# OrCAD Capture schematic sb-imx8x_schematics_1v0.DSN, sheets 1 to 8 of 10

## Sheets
1 09. LVDS LCD: size A3; title: 9. LVDS LCD; rev: 1.0; note: 8010055003
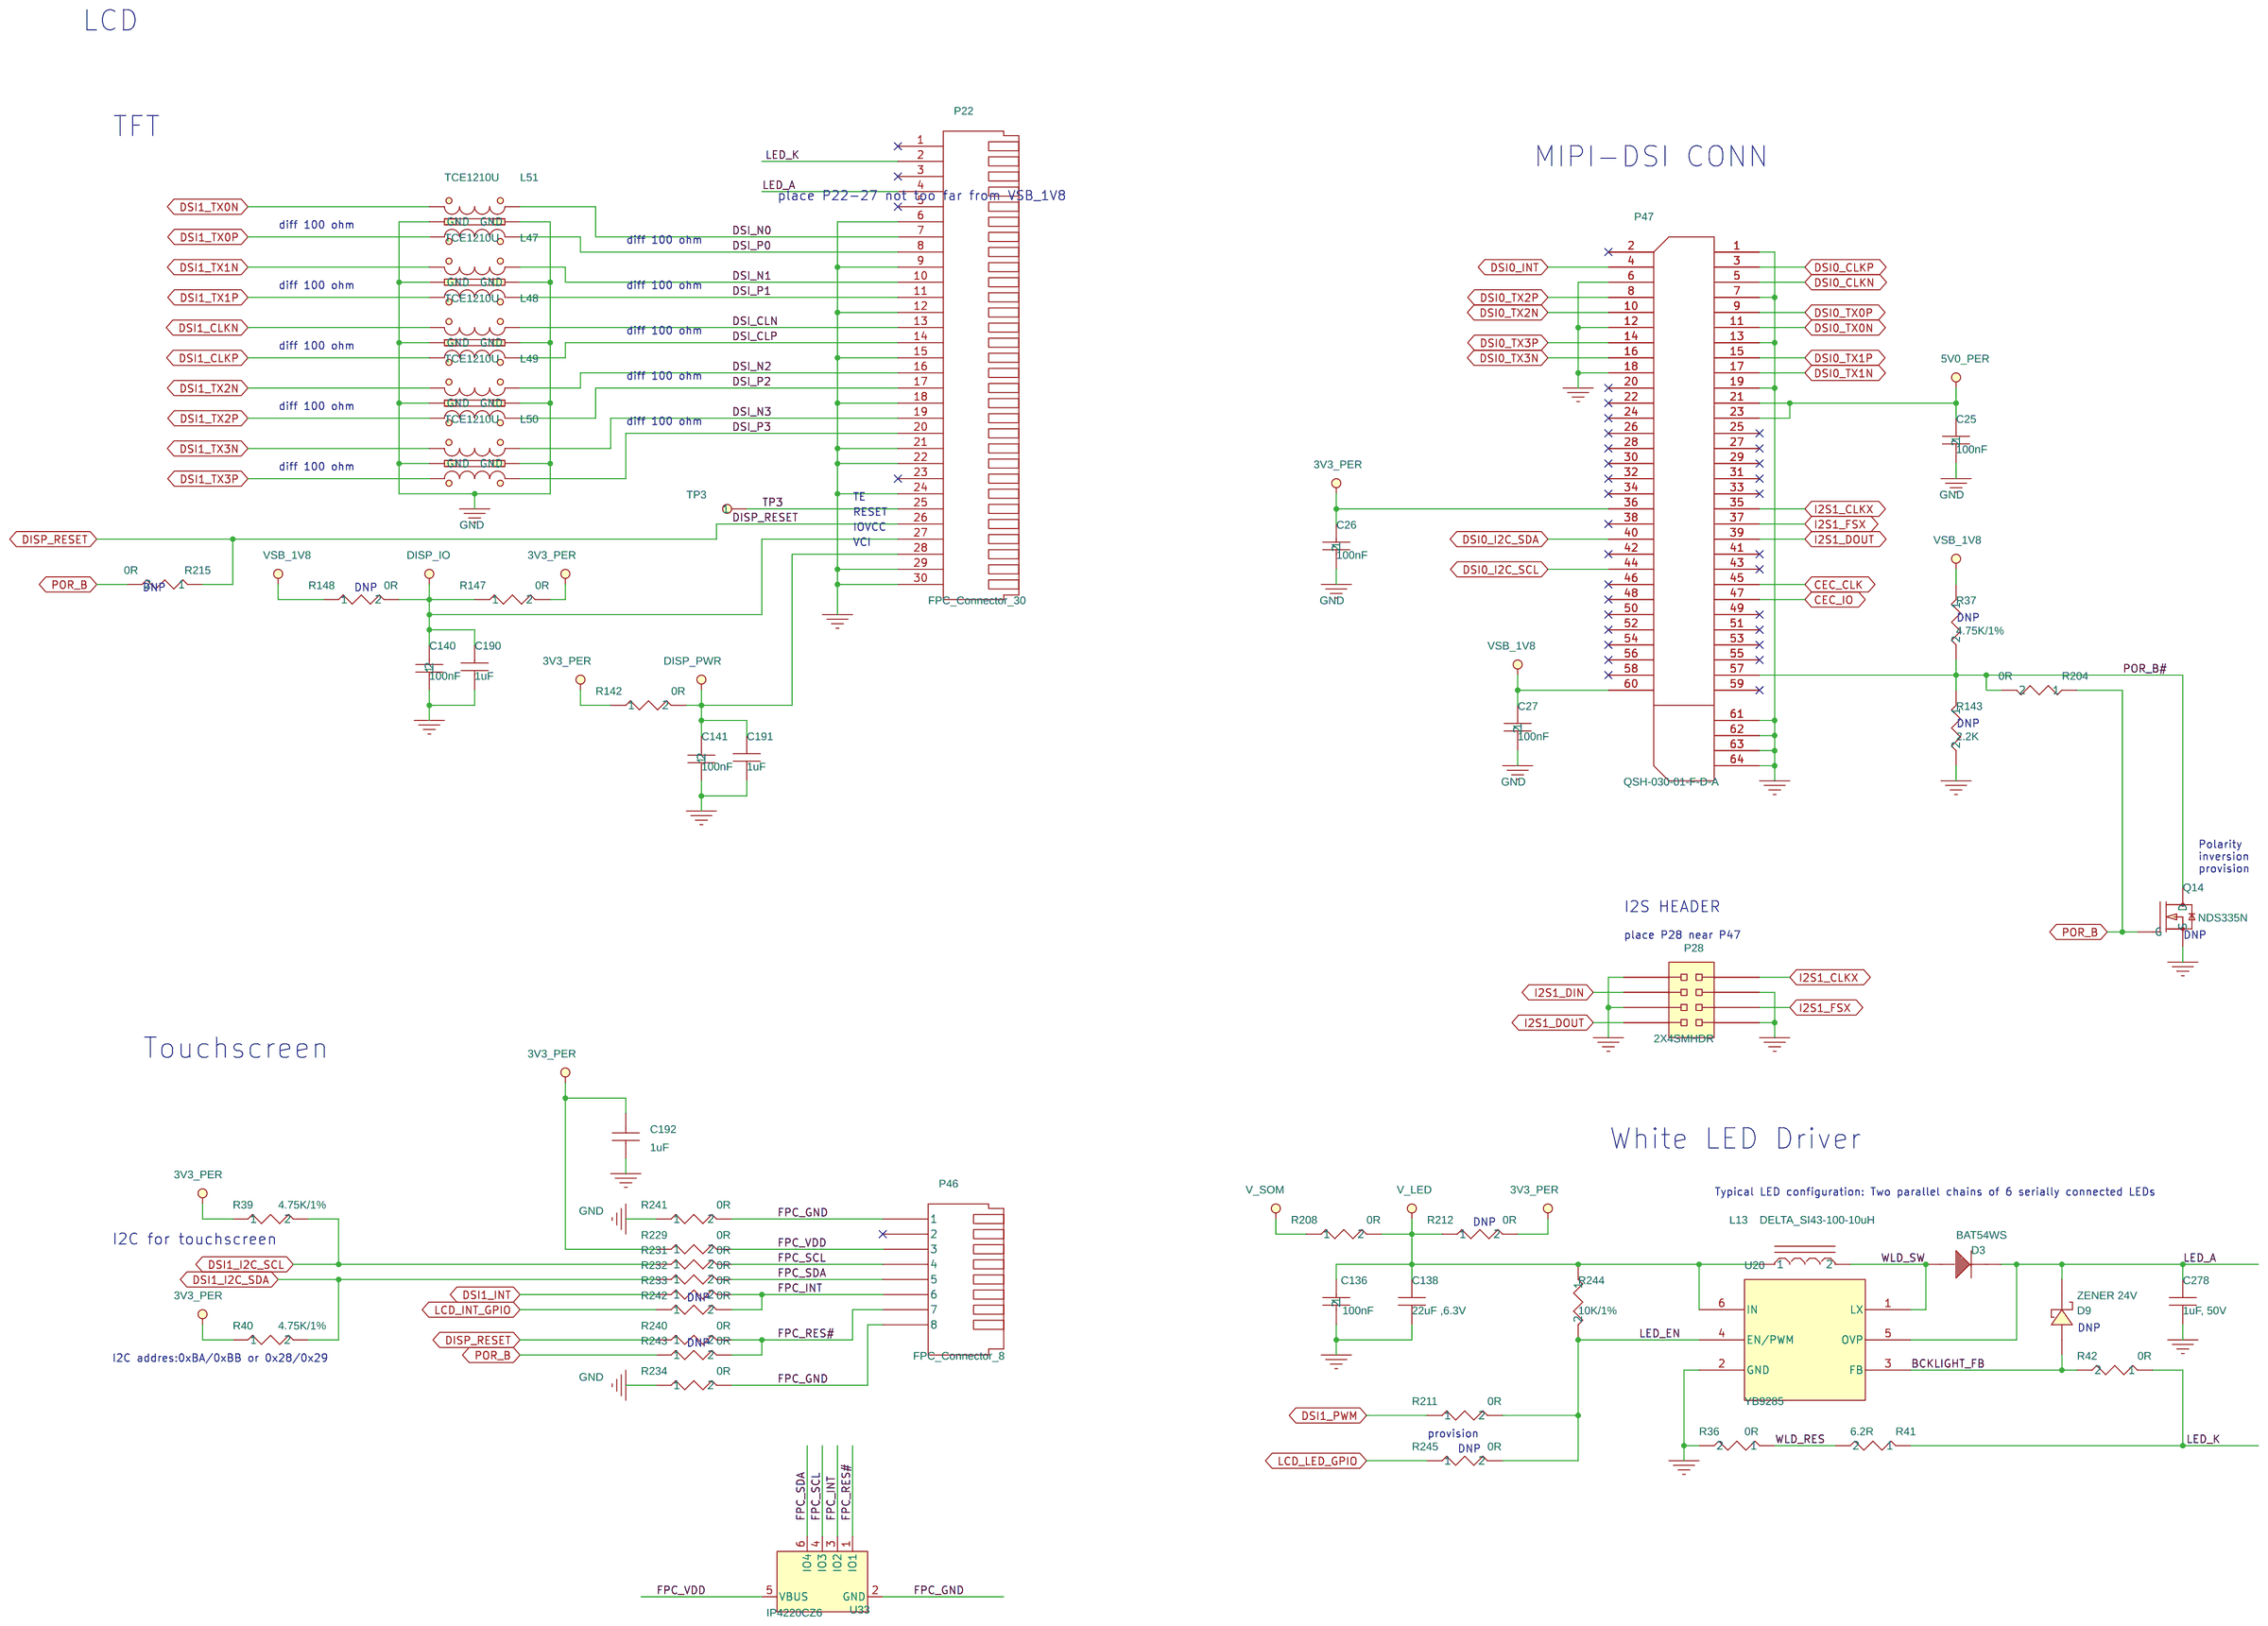
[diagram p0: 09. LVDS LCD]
2 10. MECHANICS: size B; title: 10. MECHANICS; note: 8000064001
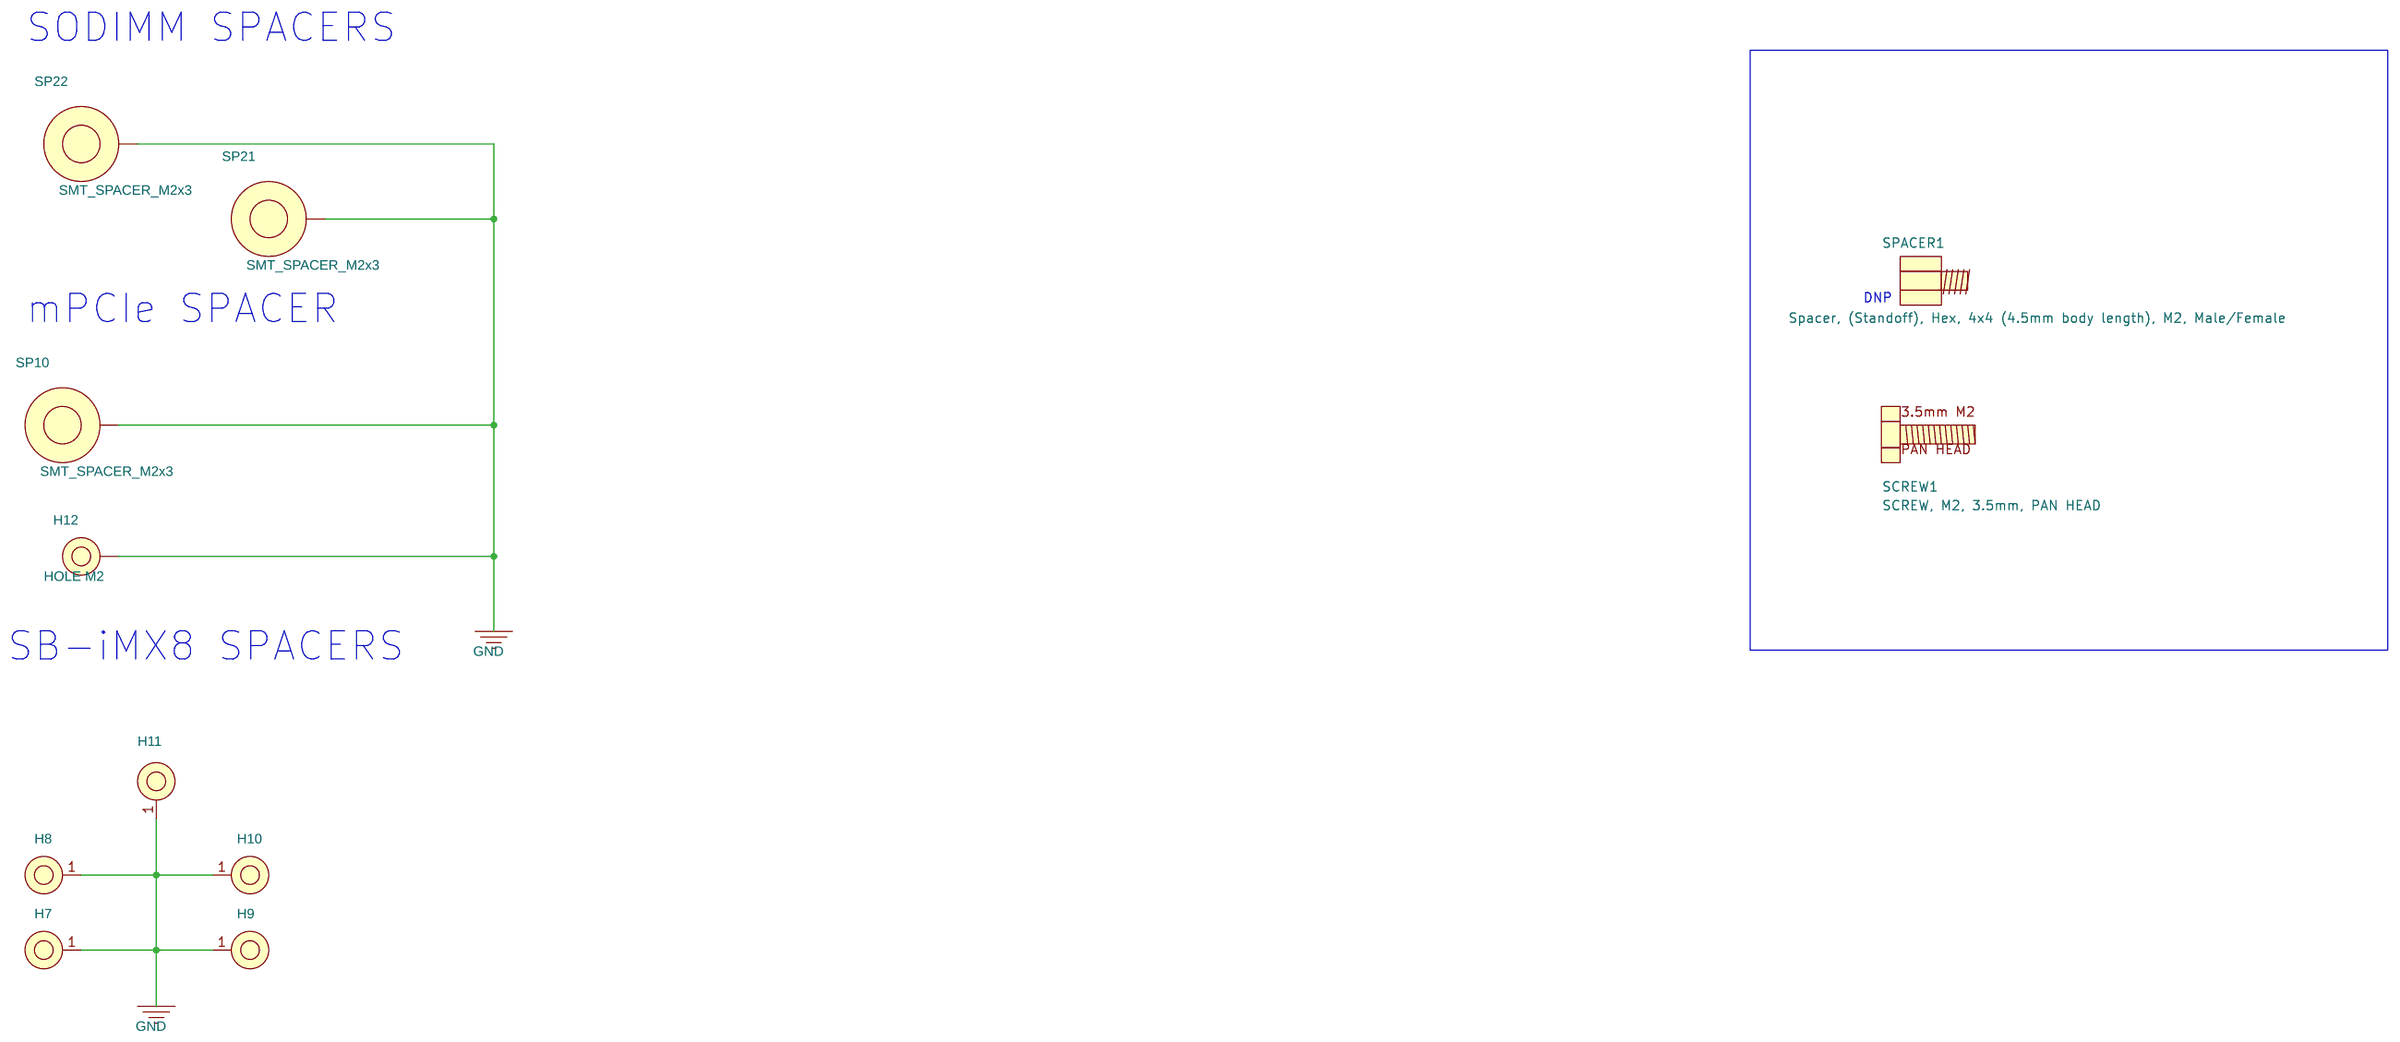
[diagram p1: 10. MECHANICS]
3 01. BLOCK & POWER DIAGRAM: size C; title: 01. BLOCK DIAGRAM
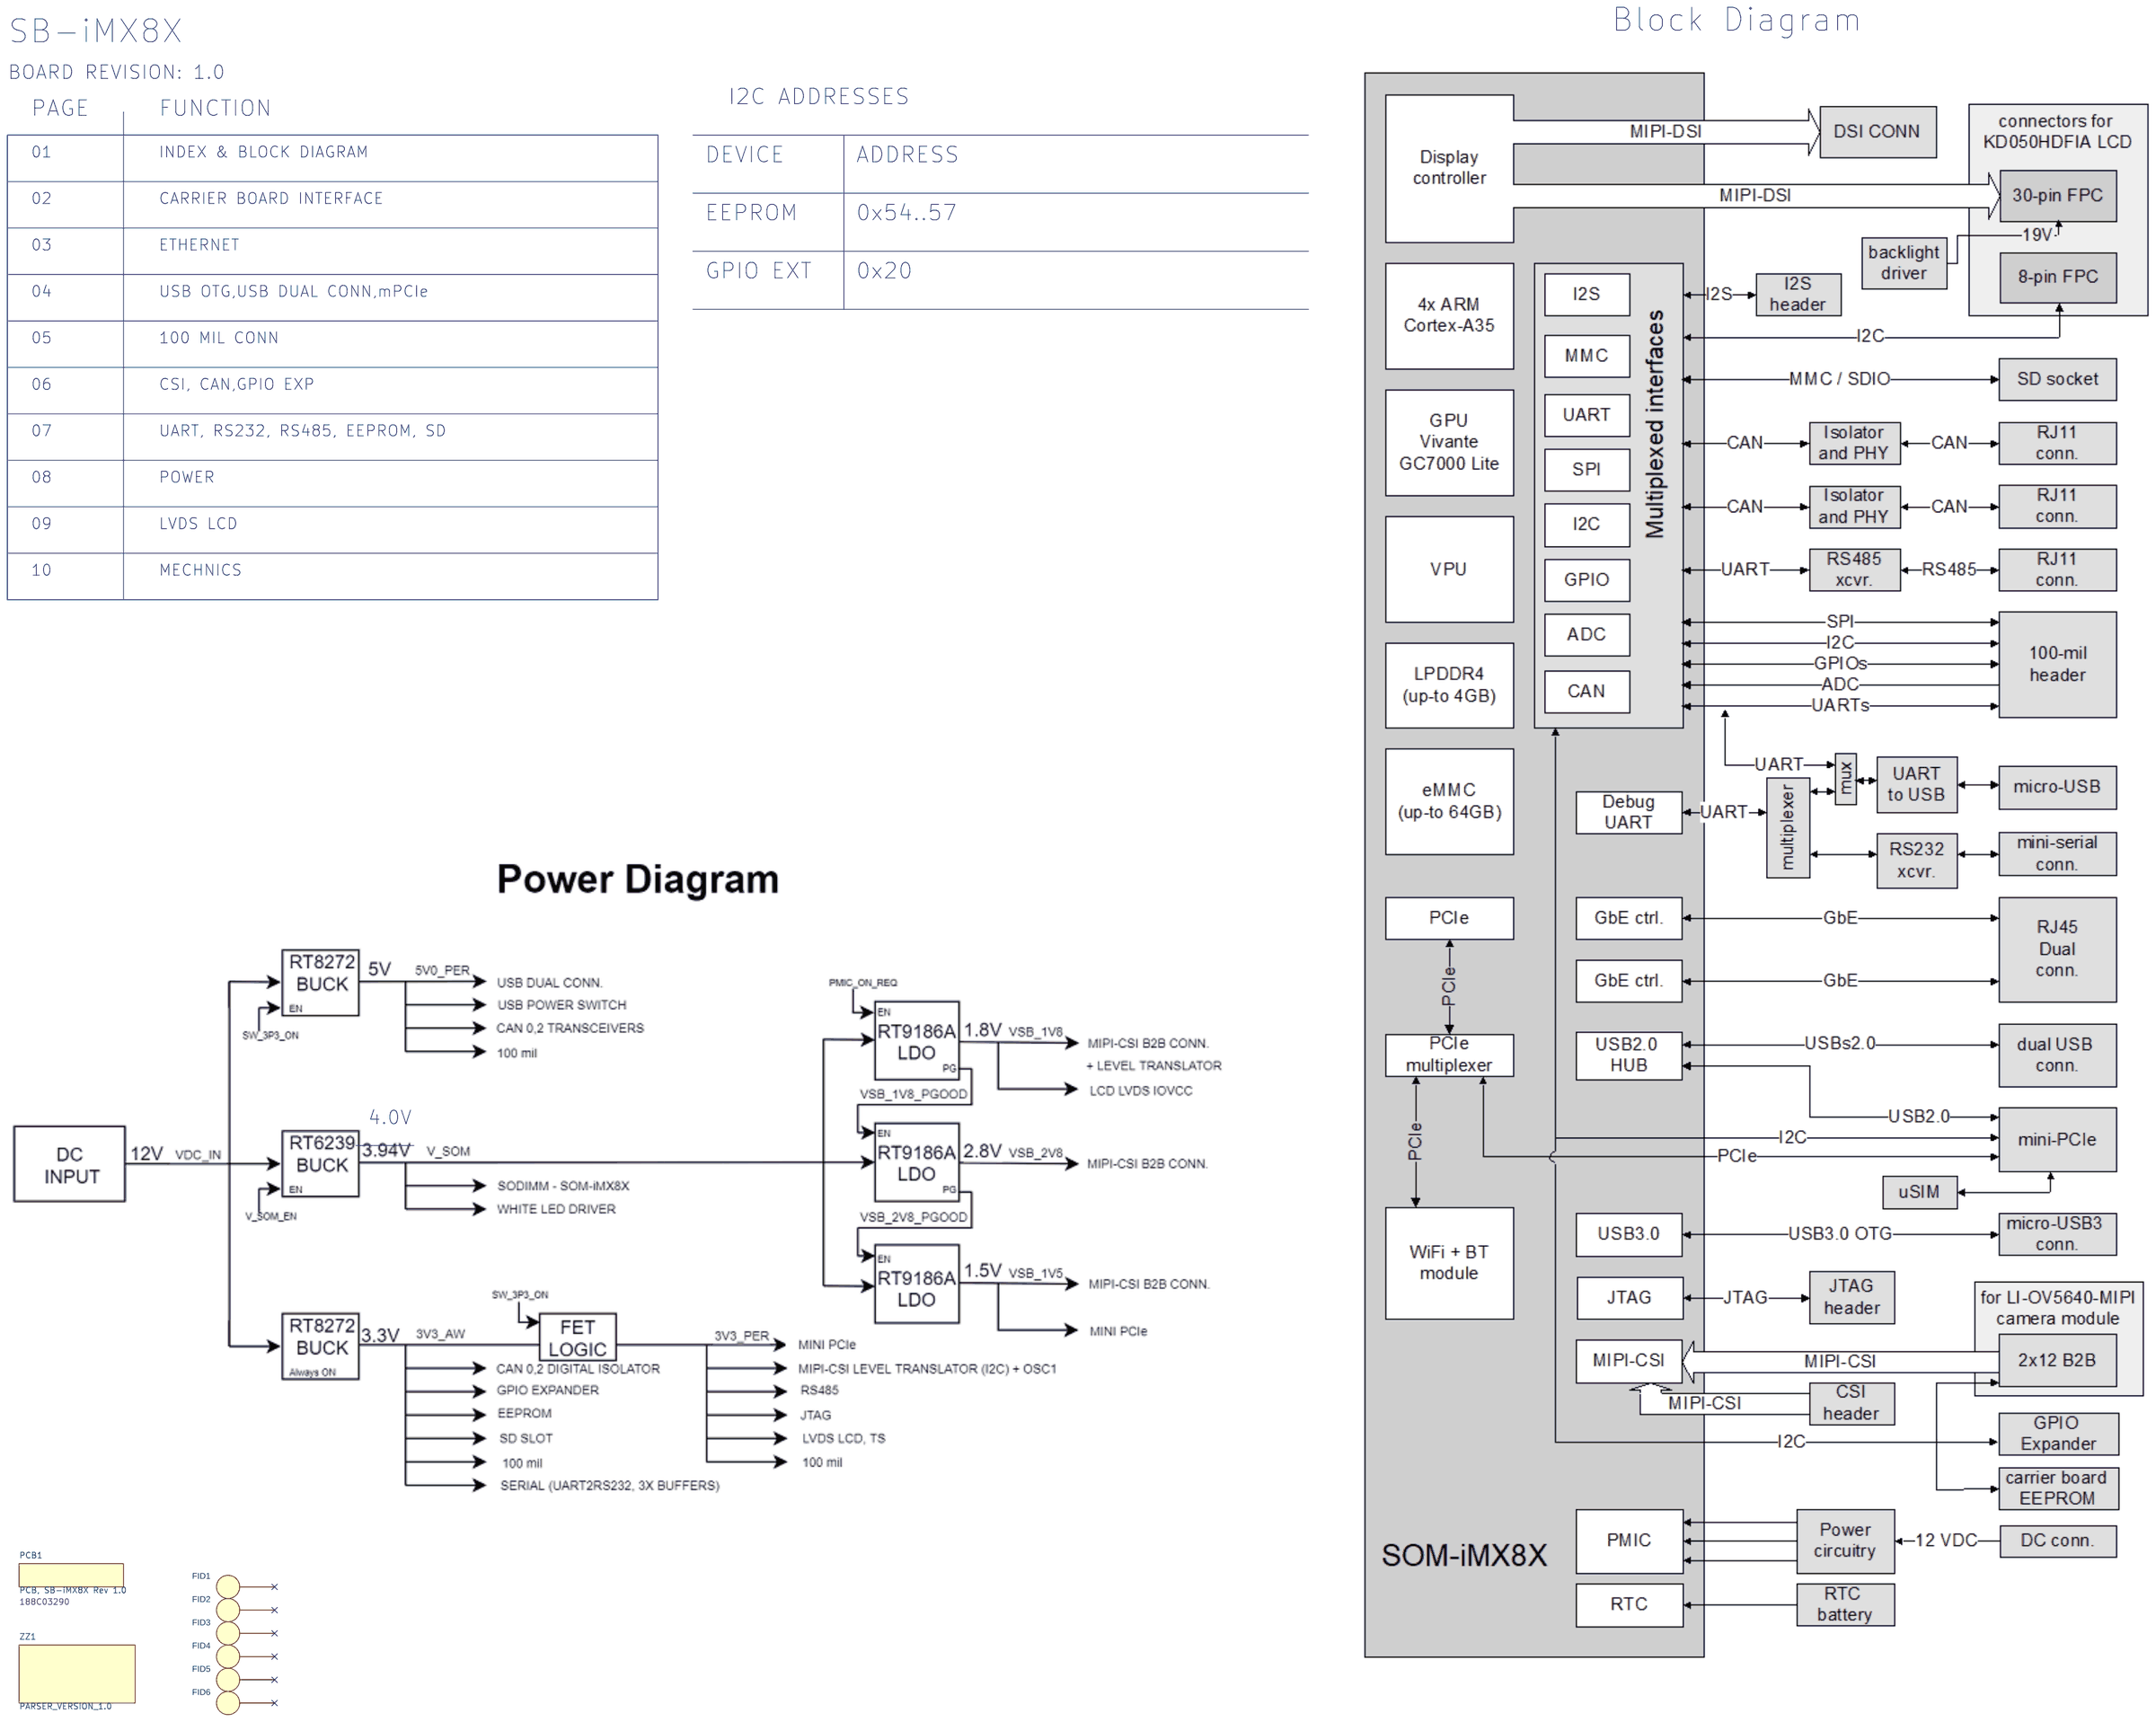
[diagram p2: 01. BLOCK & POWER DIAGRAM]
4 02. SODIMM: size C; title: 02. SODIMM; note: 8000064001
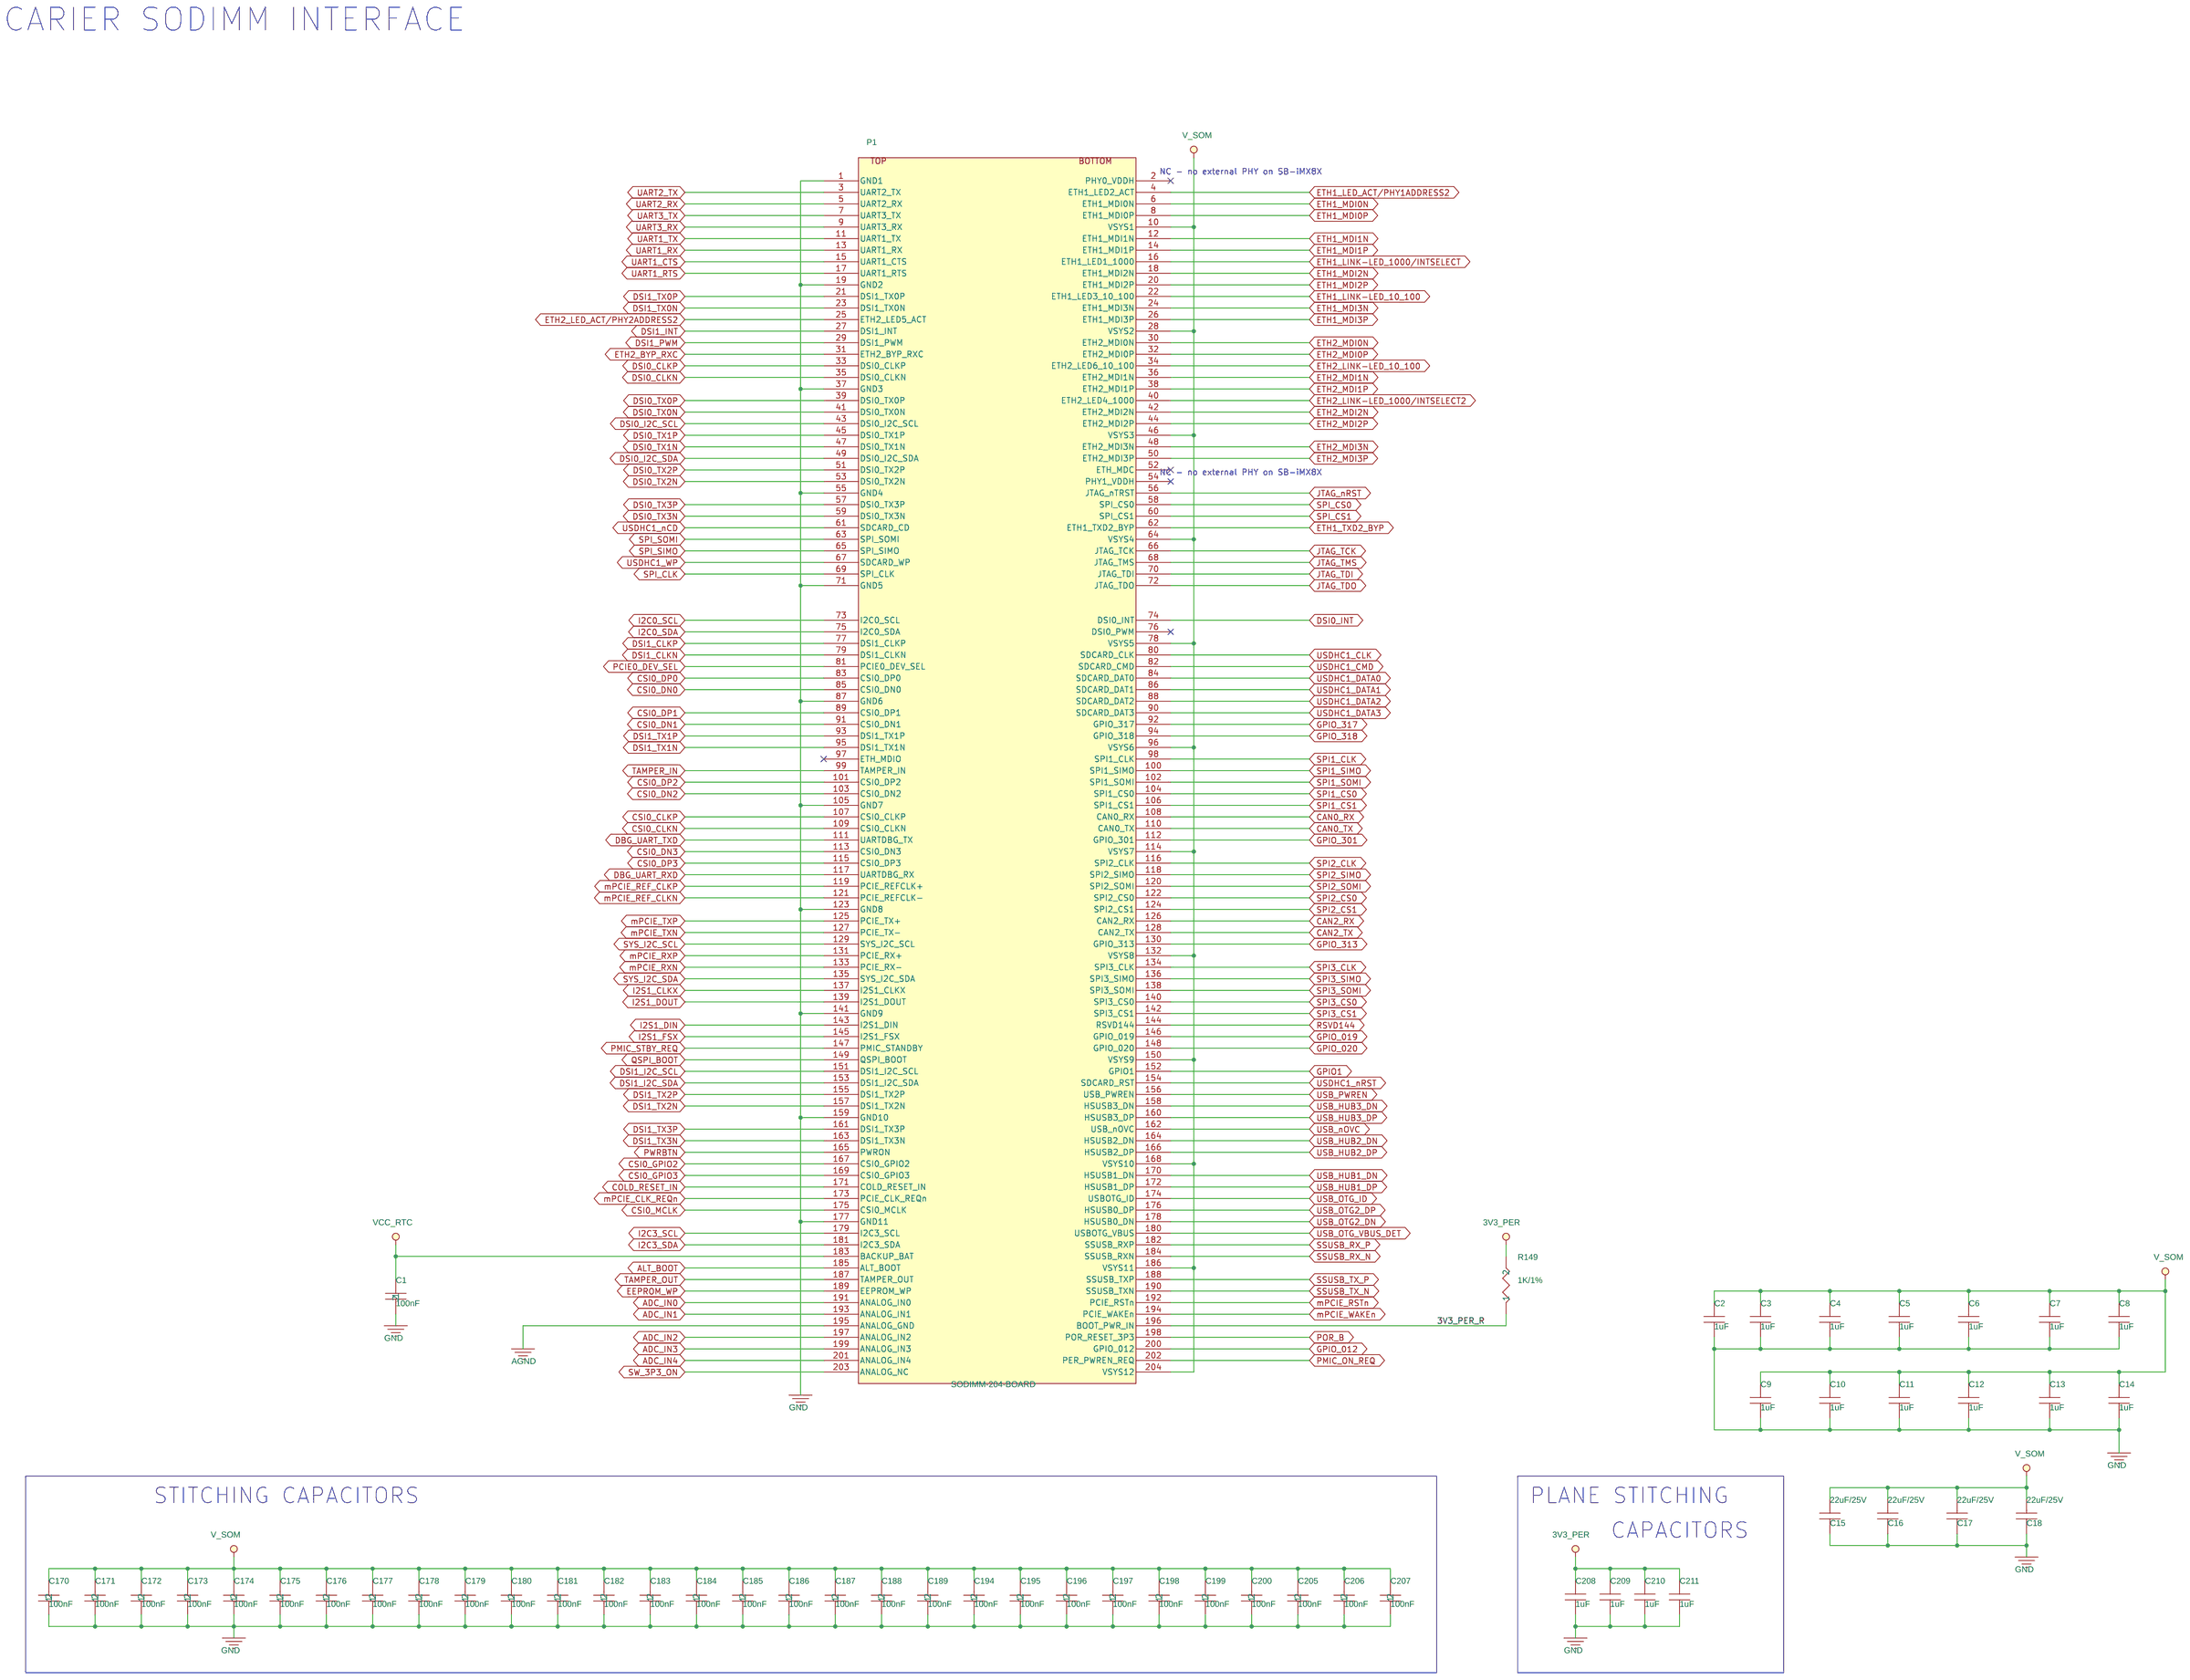
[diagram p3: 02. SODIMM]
5 03. ETHERNET 1 , 2: size B; title: 03. ETHERNET 1 , 2; note: 8000064001
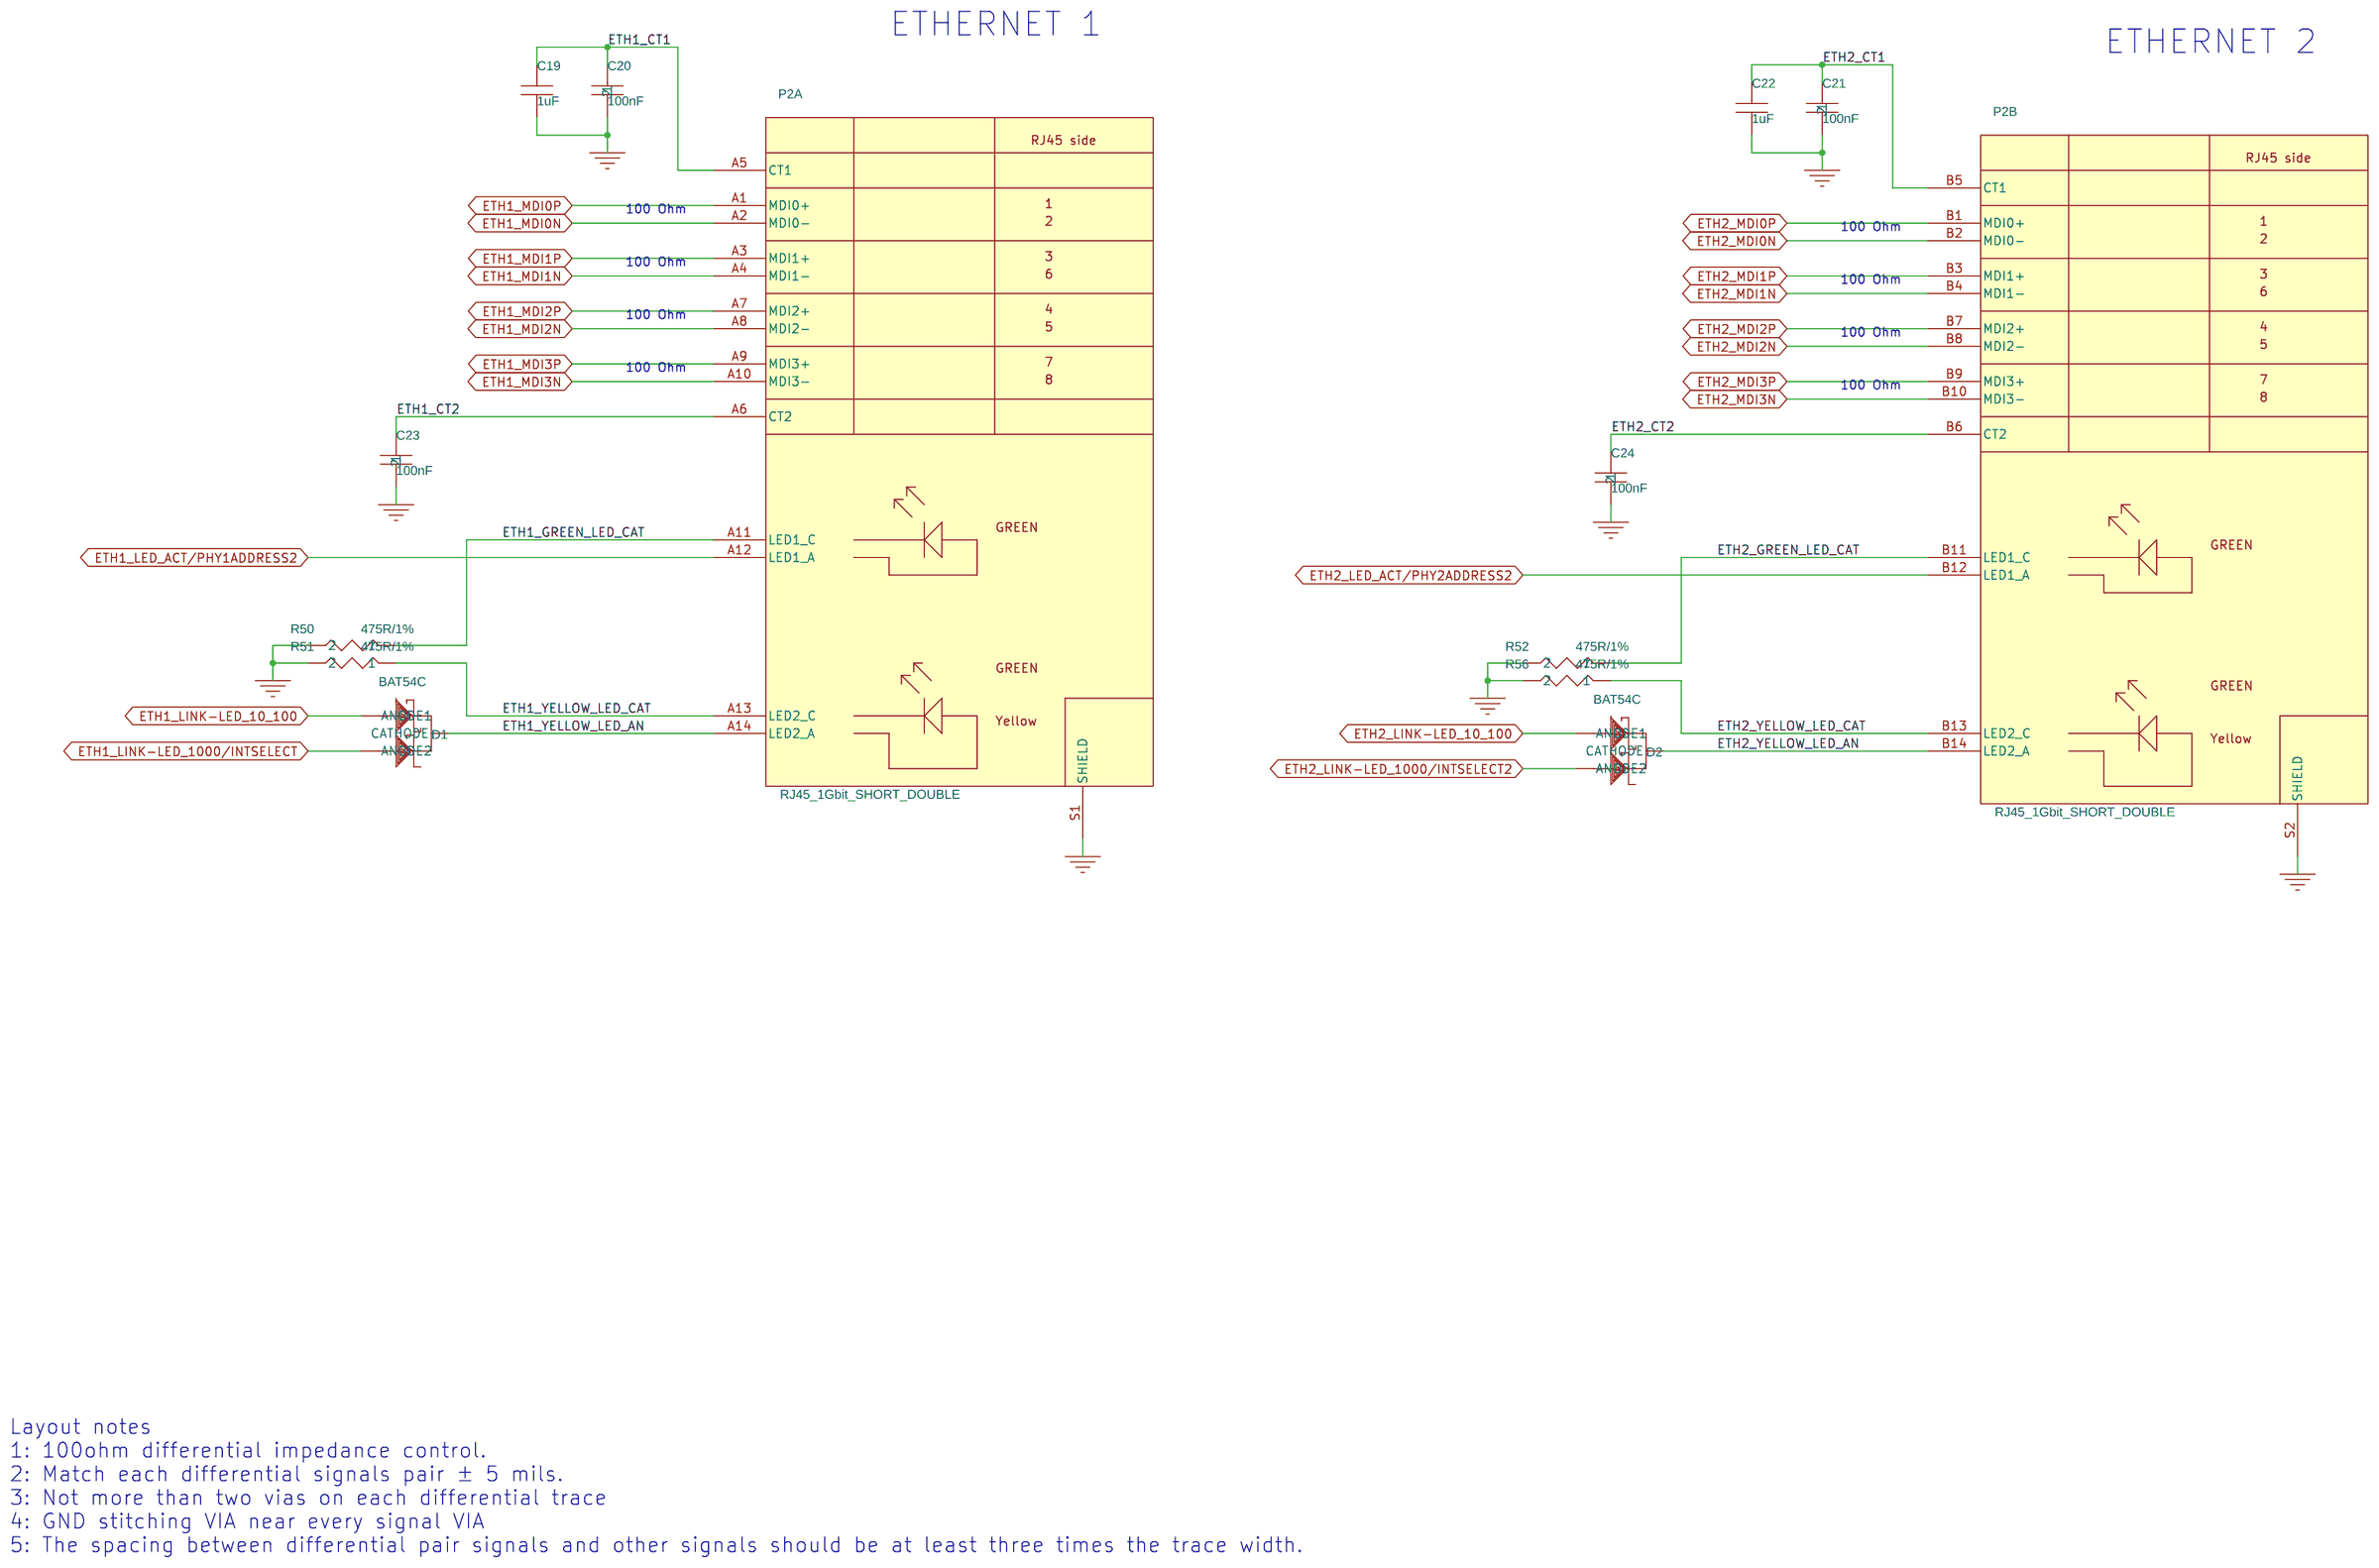
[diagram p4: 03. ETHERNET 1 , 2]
6 04. USB OTG,USB DUAL CONN,mPCIe: size C; title: 04. USB OTG,USB DUAL CONN,mPCIe
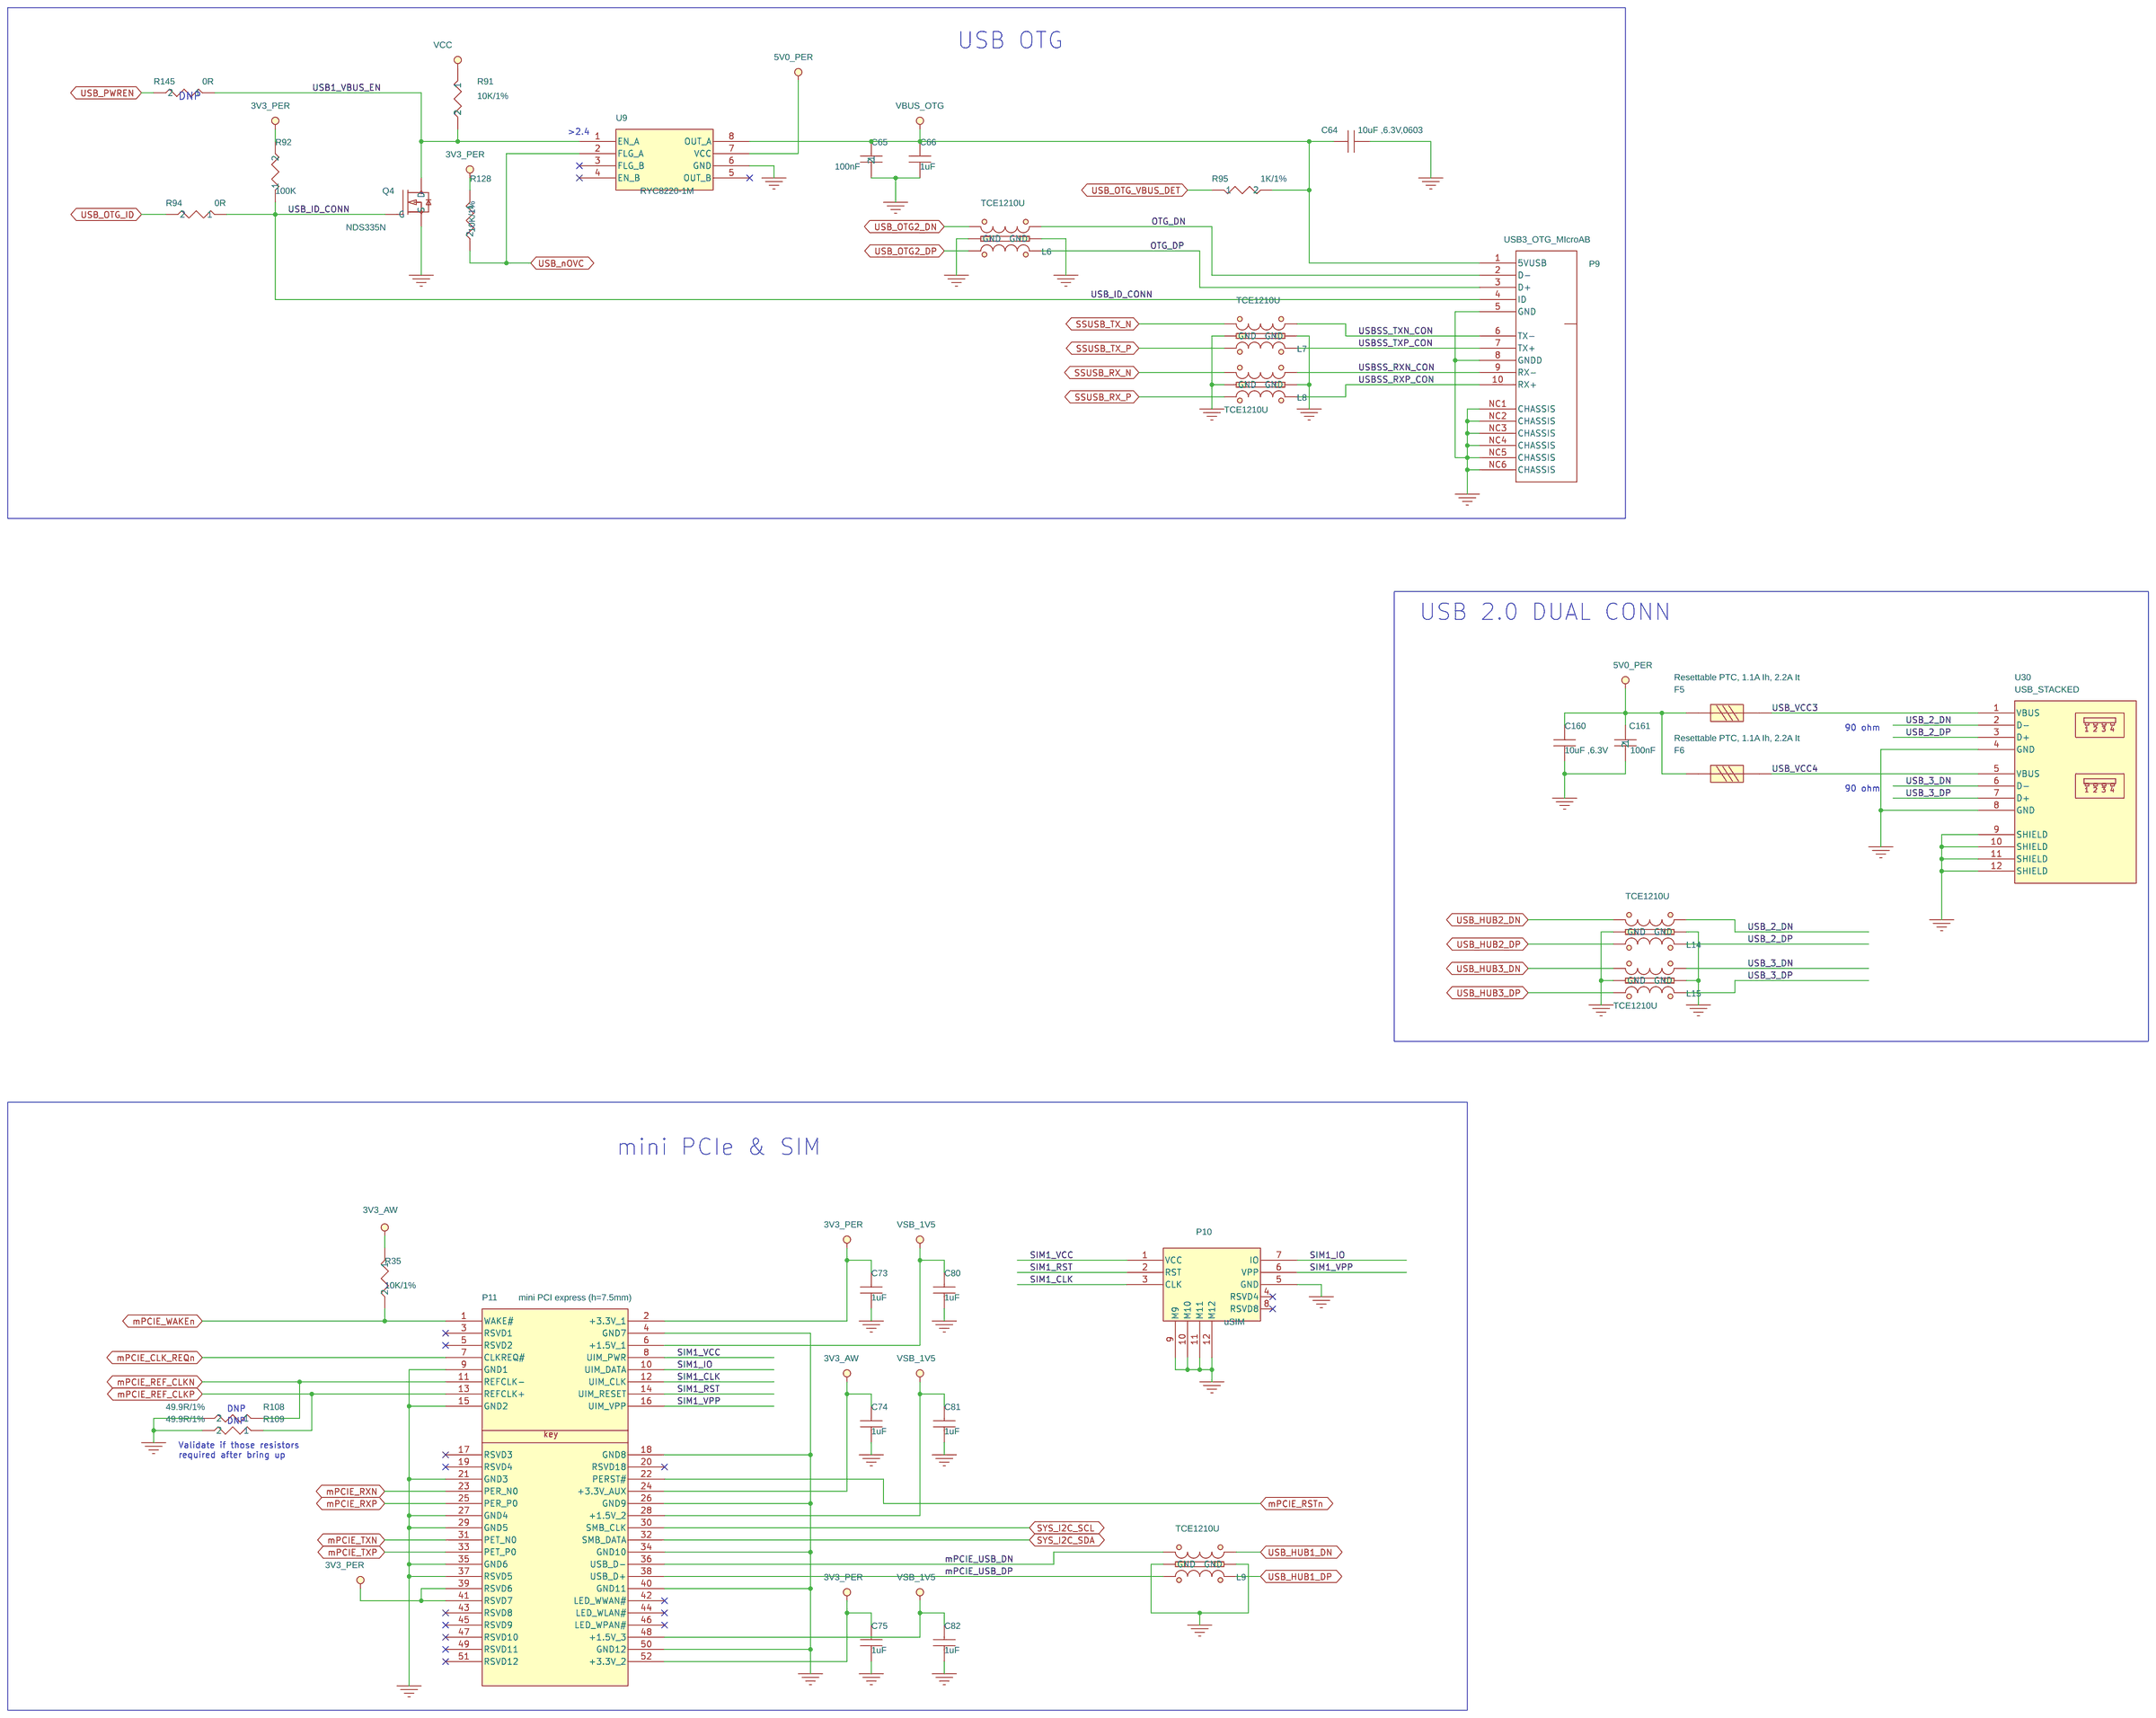
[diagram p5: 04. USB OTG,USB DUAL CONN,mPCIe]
7 05. 100 MIL CONN: size B; title: 05. 100 MIL CONN
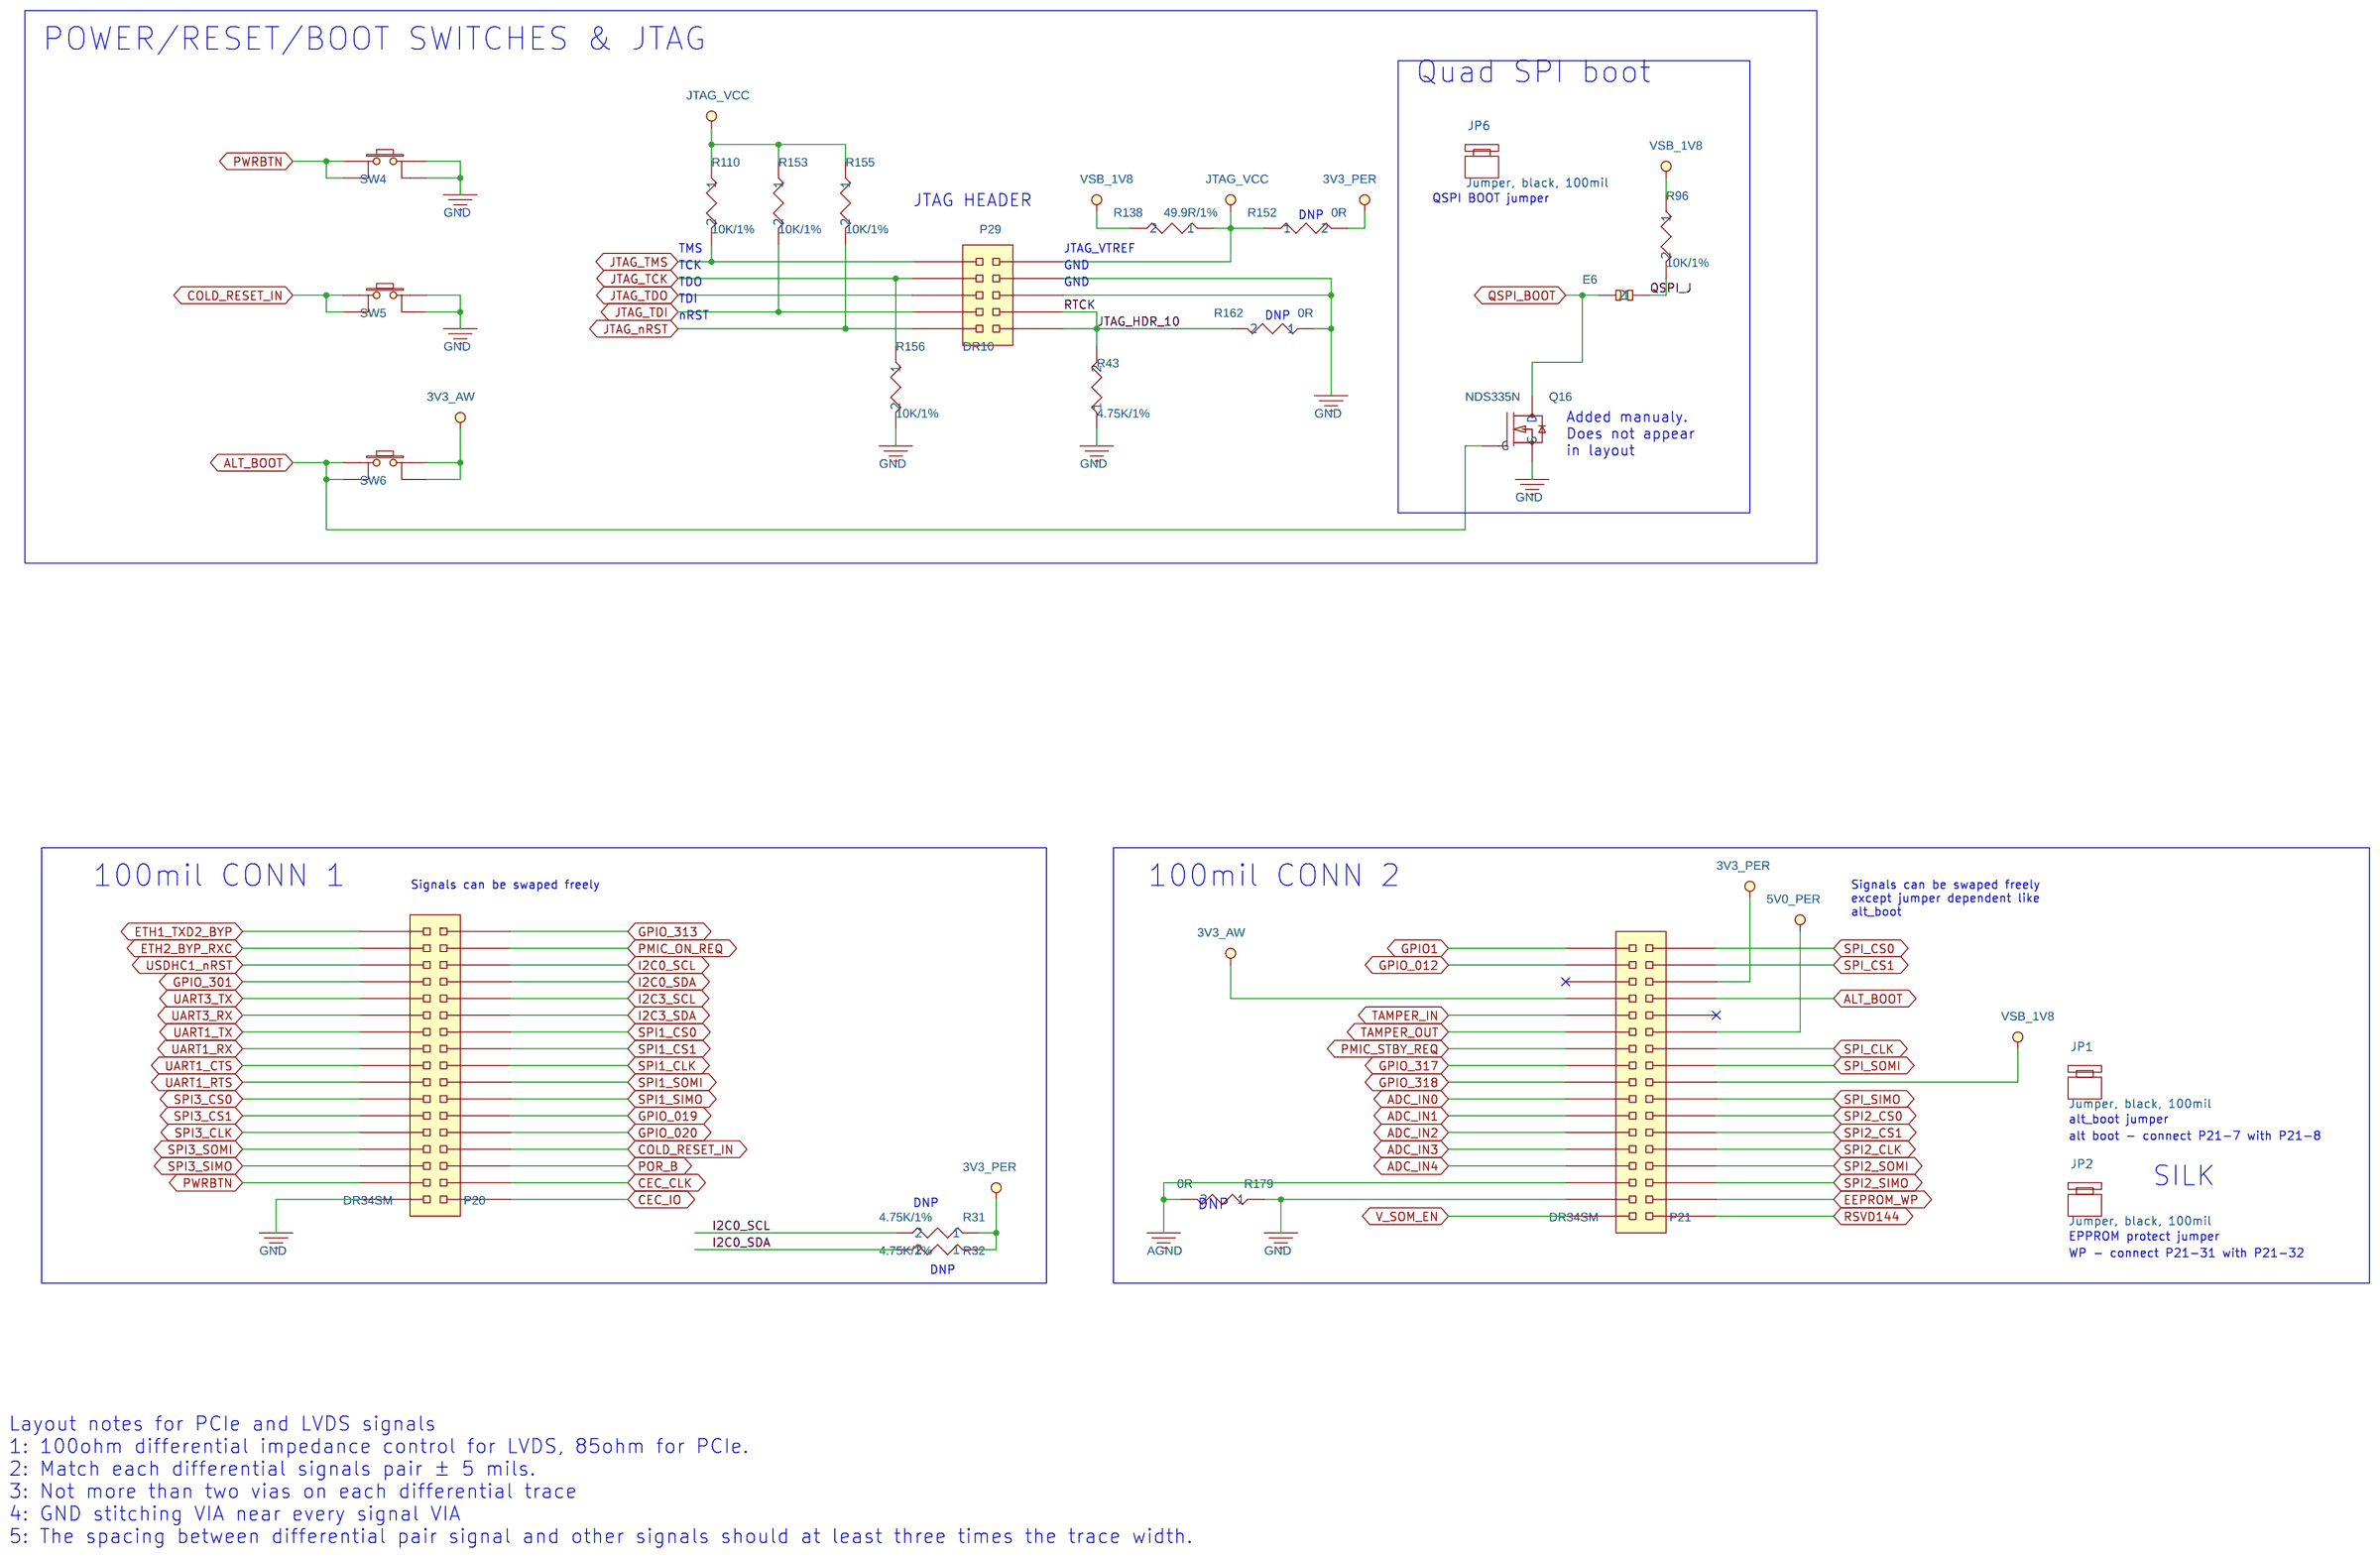
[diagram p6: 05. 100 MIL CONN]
8 06. CSI, CAN,GPIO EXP: size C; title: 06. CSI, CAN,GPIO EXP
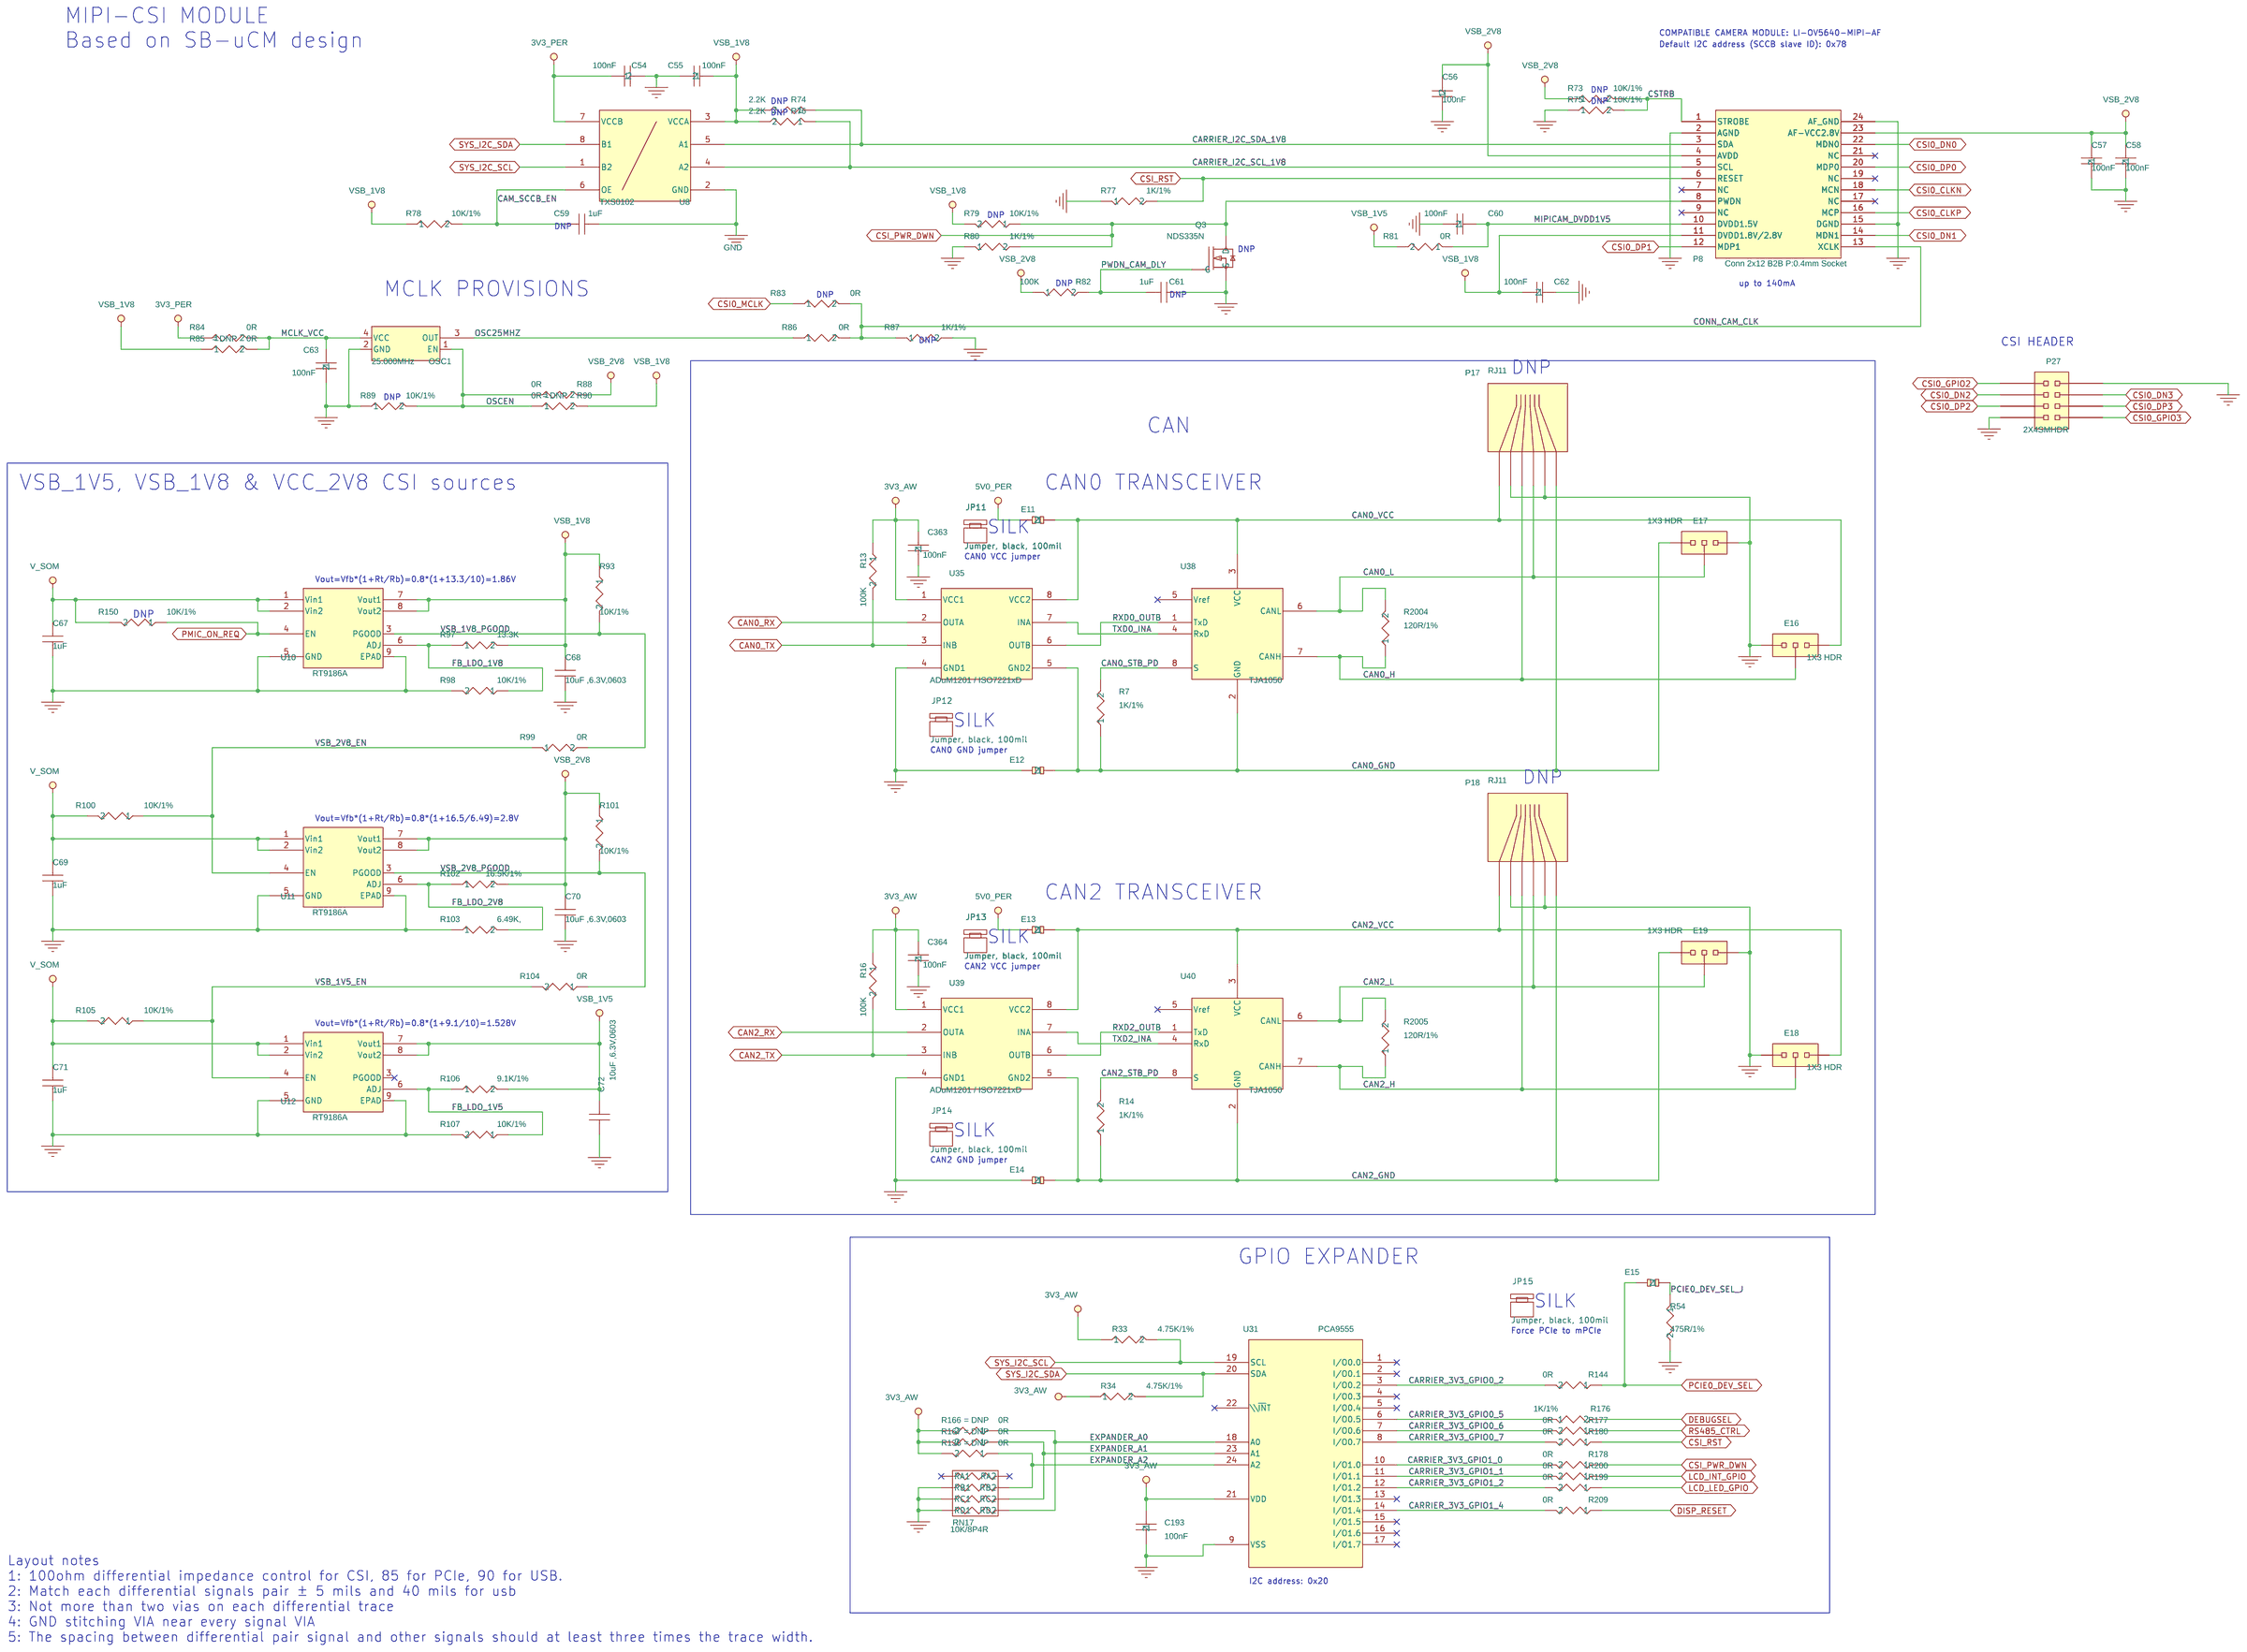
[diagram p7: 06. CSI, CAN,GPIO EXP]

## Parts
sheet 01. BLOCK & POWER DIAGRAM
FID1  FIDUCIAL  [FIDUCIAL]
FID2  FIDUCIAL  [FIDUCIAL]
FID3  FIDUCIAL  [FIDUCIAL]
FID4  FIDUCIAL  [FIDUCIAL]
FID5  FIDUCIAL  [FIDUCIAL]
FID6  FIDUCIAL  [FIDUCIAL]
PCB1  PCB, SB-iMX8X Rev 1.0
ZZ1  PARSER_VERSION_1.0
sheet 02. SODIMM
C1  100nF  [RC0402]
C2  1uF  [RC0402]
C3  1uF  [RC0402]
C4  1uF  [RC0402]
C5  1uF  [RC0402]
C6  1uF  [RC0402]
C7  1uF  [RC0402]
C8  1uF  [RC0402]
C9  1uF  [RC0402]
C10  1uF  [RC0402]
C11  1uF  [RC0402]
C12  1uF  [RC0402]
C13  1uF  [RC0402]
C14  1uF  [RC0402]
C15  22uF/25V  [C0805]
C16  22uF/25V  [C0805]
C17  22uF/25V  [C0805]
C18  22uF/25V  [C0805]
C170  100nF  [RC0402]
C171  100nF  [RC0402]
C172  100nF  [RC0402]
C173  100nF  [RC0402]
C174  100nF  [RC0402]
C175  100nF  [RC0402]
C176  100nF  [RC0402]
C177  100nF  [RC0402]
C178  100nF  [RC0402]
C179  100nF  [RC0402]
C180  100nF  [RC0402]
C181  100nF  [RC0402]
C182  100nF  [RC0402]
C183  100nF  [RC0402]
C184  100nF  [RC0402]
C185  100nF  [RC0402]
C186  100nF  [RC0402]
C187  100nF  [RC0402]
C188  100nF  [RC0402]
C189  100nF  [RC0402]
C194  100nF  [RC0402]
C195  100nF  [RC0402]
C196  100nF  [RC0402]
C197  100nF  [RC0402]
C198  100nF  [RC0402]
C199  100nF  [RC0402]
C200  100nF  [RC0402]
C205  100nF  [RC0402]
C206  100nF  [RC0402]
C207  100nF  [RC0402]
C208  1uF  [RC0402]
C209  1uF  [RC0402]
C210  1uF  [RC0402]
C211  1uF  [RC0402]
P1  SODIMM-204-BOARD  [RC0402]
R149  1K/1%  [RC0402]
sheet 03. ETHERNET 1 , 2
C19  1uF  [RC0402]
C20  100nF  [RC0402]
C21  100nF  [RC0402]
C22  1uF  [RC0402]
C23  100nF  [RC0402]
C24  100nF  [RC0402]
D1  BAT54C  [SOT23]
D2  BAT54C  [SOT23]
P2  RJ45_1Gbit_SHORT_DOUBLE  [RJTR1GRATHX2]  (sections A,B)
R50  475R/1%  [RC0402]
R51  475R/1%  [RC0402]
R52  475R/1%  [RC0402]
R56  475R/1%  [RC0402]
sheet 04. USB OTG,USB DUAL CONN,mPCIe
C64  10uF ,6.3V,0603  [C0603-08]
C65  100nF  [RC0402]
C66  1uF  [RC0402]
C73  1uF  [RC0402]
C74  1uF  [RC0402]
C75  1uF  [RC0402]
C80  1uF  [RC0402]
C81  1uF  [RC0402]
C82  1uF  [RC0402]
C160  10uF ,6.3V  [C0603-08]
C161  100nF  [RC0402]
F5  Resettable PTC, 1.1A Ih, 2.2A It  [FUSE-1206]
F6  Resettable PTC, 1.1A Ih, 2.2A It  [FUSE-1206]
L6  TCE1210U  [EMI1012-ESD]
L7  TCE1210U  [EMI1012-ESD]
L8  TCE1210U  [EMI1012-ESD]
L9  TCE1210U  [EMI1012-ESD]
L14  TCE1210U  [EMI1012-ESD]
L15  TCE1210U  [EMI1012-ESD]
P9  USB3_OTG_MIcroAB  [MICRO-USB3-AB-RA-SM]
P10  uSIM  [SKT-MicroSIM6-SM]
P11  mini PCI express (h=7.5mm)  [MINIPCIE-4]
Q4  NDS335N  [SOT23]
R35  10K/1%  [RC0402]
R91  10K/1%  [RC0402]
R92  100K  [RC0402]
R94  0R  [RC0402]
R95  1K/1%  [RC0402]
R108  49.9R/1%  [RC0402]
R109  49.9R/1%  [RC0402]
R128  10K/1%  [RC0402]
R145  0R  [RC0402]
U9  RYC8220-1M  [SO-8-150]
U30  USB_STACKED  [USB-2XA-TH]
sheet 05. 100 MIL CONN
E6  HDR1X2  [1X2THHDR]
JP1  Jumper, black, 100mil
JP2  Jumper, black, 100mil
JP6  Jumper, black, 100mil
P20  DR34SM  [2X17SMHDR]
P21  DR34SM  [2X17SMHDR]
P29  DR10  [2X5THHDR]
Q16  NDS335N  [SOT23]
R31  4.75K/1%  [RC0402]
R32  4.75K/1%  [RC0402]
R43  4.75K/1%  [RC0402]
R96  10K/1%  [RC0402]
R110  10K/1%  [RC0402]
R138  49.9R/1%  [RC0402]
R152  0R  [RC0402]
R153  10K/1%  [RC0402]
R155  10K/1%  [RC0402]
R156  10K/1%  [RC0402]
R162  0R  [RC0402]
R179  0R  [RC0402]
SW4  PushB  [TACTSW6x6SM]
SW5  PushB  [TACTSW6x6SM]
SW6  PushB  [TACTSW6x6SM]
sheet 06. CSI, CAN,GPIO EXP
C54  100nF  [RC0402]
C55  100nF  [RC0402]
C56  100nF  [RC0402]
C57  100nF  [RC0402]
C58  100nF  [RC0402]
C59  1uF  [RC0402]
C60  100nF  [RC0402]
C61  1uF  [RC0402]
C62  100nF  [RC0402]
C63  100nF  [RC0402]
C67  1uF  [RC0402]
C68  10uF ,6.3V,0603  [C0603-08]
C69  1uF  [RC0402]
C70  10uF ,6.3V,0603  [C0603-08]
C71  1uF  [RC0402]
C72  10uF ,6.3V,0603  [C0603-08]
C193  100nF  [RC0402]
C363  100nF  [RC0402]
C364  100nF  [RC0402]
E11  HDR1X2  [1X2THHDR]
E12  HDR1X2  [1X2THHDR]
E13  HDR1X2  [1X2THHDR]
E14  HDR1X2  [1X2THHDR]
E15  HDR1X2  [1X2THHDR]
E16  1X3 HDR  [2X4SMHDR]
E17  1X3 HDR  [2X4SMHDR]
E18  1X3 HDR  [2X4SMHDR]
E19  1X3 HDR  [2X4SMHDR]
JP11  Jumper, black, 100mil
JP12  Jumper, black, 100mil
JP13  Jumper, black, 100mil
JP14  Jumper, black, 100mil
JP15  Jumper, black, 100mil
OSC1  25.000MHz  [OSC3225]
P8  Conn 2x12 B2B P:0.4mm Socket  [B2B04M2X12R]
P17  RJ11  [RJ11TH6-6]
P18  RJ11  [RJ11TH6-6]
P27  2X4SMHDR  [2X4SMHDR]
Q3  NDS335N  [SOT23]
R7  1K/1%  [RC0402]
R13  100K  [RC0402]
R14  1K/1%  [RC0402]
R16  100K  [RC0402]
R33  4.75K/1%  [RC0402]
R34  4.75K/1%  [RC0402]
R54  475R/1%  [RC0402]
R73  10K/1%  [RC0402]
R74  2.2K  [RC0402]
R75  10K/1%  [RC0402]
R76  2.2K  [RC0402]
R77  1K/1%  [RC0402]
R78  10K/1%  [RC0402]
R79  10K/1%  [RC0402]
R80  1K/1%  [RC0402]
R81  0R  [RC0402]
R82  100K  [RC0402]
R83  0R  [RC0402]
R84  0R  [RC0402]
R85  0R  [RC0402]
R86  0R  [RC0402]
R87  1K/1%  [RC0402]
R88  0R  [RC0402]
R89  10K/1%  [RC0402]
R90  0R  [RC0402]
R93  10K/1%  [RC0402]
R97  13.3K  [RC0402]
R98  10K/1%  [RC0402]
R99  0R  [RC0402]
R100  10K/1%  [RC0402]
R101  10K/1%  [RC0402]
R102  16.5K/1%  [RC0402]
R103  6.49K,  [RC0402]
R104  0R  [RC0402]
R105  10K/1%  [RC0402]
R106  9.1K/1%  [RC0402]
R107  10K/1%  [RC0402]
R136  0R  [RC0402]
R144  0R  [RC0402]
R150  10K/1%  [RC0402]
R166  0R  [RC0402]
R167  0R  [RC0402]
R176  1K/1%  [RC0402]
R177  0R  [RC0402]
R178  0R  [RC0402]
R180  0R  [RC0402]
R199  0R  [RC0402]
R200  0R  [RC0402]
R209  0R  [RC0402]
R2004  120R/1%  [RC0603]
R2005  120R/1%  [RC0603]
RN17  10K/8P4R  [RESNET8P0805]
U8  TXS0102  [MO-187DA-8]
U10  RT9186A  [DFN3x3-8]
U11  RT9186A  [DFN3x3-8]
U12  RT9186A  [DFN3x3-8]
U31  PCA9555  [QFN4x4-24]
U35  ADuM1201 / ISO7221xD  [SO-8-150]
U38  TJA1050  [SO-8-150]
U39  ADuM1201 / ISO7221xD  [SO-8-150]
U40  TJA1050  [SO-8-150]
sheet 09. LVDS LCD
C25  100nF  [RC0402]
C26  100nF  [RC0402]
C27  100nF  [RC0402]
C136  100nF  [RC0402]
C138  22uF ,6.3V  [RC0603]
C140  100nF  [RC0402]
C141  100nF  [RC0402]
C190  1uF  [RC0402]
C191  1uF  [RC0402]
C192  1uF  [RC0402]
C278  1uF, 50V  [RC0603]
D3  BAT54WS  [SOD-323]
D9  ZENER 24V  [SOD-123]
L13  DELTA_SI43-100-10uH  [IND4x4x2_5]
L47  TCE1210U  [EMI1012-ESD]
L48  TCE1210U  [EMI1012-ESD]
L49  TCE1210U  [EMI1012-ESD]
L50  TCE1210U  [EMI1012-ESD]
L51  TCE1210U  [EMI1012-ESD]
P22  FPC_Connector_30  [FPC_30]
P28  2X4SMHDR  [2X4SMHDR]
P46  FPC_Connector_8  [FPC_8]
P47  QSH-030-01-F-D-A  [TBD]
Q14  NDS335N  [SOT23]
R36  0R  [RC0402]
R37  4.75K/1%  [RC0402]
R39  4.75K/1%  [RC0402]
R40  4.75K/1%  [RC0402]
R41  6.2R  [RC0402]
R42  0R  [RC0402]
R142  0R  [RC0402]
R143  2.2K  [RC0402]
R147  0R  [RC0402]
R148  0R  [RC0402]
R204  0R  [RC0402]
R208  0R  [RC0402]
R211  0R  [RC0402]
R212  0R  [RC0402]
R215  0R  [RC0402]
R229  0R  [RC0402]
R231  0R  [RC0402]
R232  0R  [RC0402]
R233  0R  [RC0402]
R234  0R  [RC0402]
R240  0R  [RC0402]
R241  0R  [RC0402]
R242  0R  [RC0402]
R243  0R  [RC0402]
R244  10K/1%  [RC0402]
R245  0R  [RC0402]
TP3  TESTPOINT  [TESTPOINT]
U20  YB9285  [SOT23-6L]
U33  IP4220CZ6  [SOT23-6L]
sheet 10. MECHANICS
H7  MechHole  [M3PAD]
H8  MechHole  [M3PAD]
H9  MechHole  [M3PAD]
H10  MechHole  [M3PAD]
H11  MechHole  [M3PAD]
H12  HOLE M2  [M2PAD]
SCREW1  SCREW, M2, 3.5mm, PAN HEAD  [NONE]
SP10  SMT_SPACER_M2x3  [MINIPCIE-4-Spacer]
SP21  SMT_SPACER_M2x3  [MINIPCIE-4-Spacer]
SP22  SMT_SPACER_M2x3  [MINIPCIE-4-Spacer]
SPACER1  Spacer, (Standoff), Hex, 4x4 (4.5mm body length), M2, Male/Female  [NONE]

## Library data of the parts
FID1-FID6 = TESTPOINT_2: CLABCONF0: = DNP
PCB1 = PCB,_EM-X270_Rev_1_0.1: CLABCONF0: = SB-iMX8X; P/N: 188C03290
ZZ1 = PARSER_VERSION_1_1.0: CLABCONF0: = DNP
C1 = 100nF,_10V,_X7R,_10%,_0402_13: CLABCONF0: = SB-iMX8X
C2-C14 C19 C22 C66 C67 C69 C71 C73-C75 C80-C82 C190-C192 C208-C211 = 1uF,X5R,6.3V,0402: CLABCONF0: = SB-iMX8X
C15 = Cap.,22uF,25V,_0805: CLABCONF0: = SB-iMX8X
C16 = Cap.,22uF,25V,_0805_3: CLABCONF0: = SB-iMX8X
C17 = Cap.,22uF,25V,_0805_2: CLABCONF0: = SB-iMX8X
C18 = Cap.,22uF,25V,_0805_1: CLABCONF0: = SB-iMX8X
C170 = 100nF,_10V,_X7R,_10%,_0402_19: CLABCONF0: = SB-iMX8X
C141 C171 = 100nF,_10V,_X7R,_10%,_0402_2: CLABCONF0: = SB-iMX8X
C172 = 100nF,_10V,_X7R,_10%,_0402_17: CLABCONF0: = SB-iMX8X
C54 C65 C140 C173 = 100nF,_10V,_X7R,_10%,_0402: CLABCONF0: = SB-iMX8X
C60 C174 = 100nF,_10V,_X7R,_10%,_0402_9: CLABCONF0: = SB-iMX8X
C175 = 100nF,_10V,_X7R,_10%,_0402_24: CLABCONF0: = SB-iMX8X
C25 C62 C176 = 100nF,_10V,_X7R,_10%,_0402_5: CLABCONF0: = SB-iMX8X
C177 = 100nF,_10V,_X7R,_10%,_0402_21: CLABCONF0: = SB-iMX8X
C55 C178 = 100nF,_10V,_X7R,_10%,_0402_6: CLABCONF0: = SB-iMX8X
C179 = 100nF,_10V,_X7R,_10%,_0402_30: CLABCONF0: = SB-iMX8X
C180 = 100nF,_10V,_X7R,_10%,_0402_23: CLABCONF0: = SB-iMX8X
C181 = 100nF,_10V,_X7R,_10%,_0402_16: CLABCONF0: = SB-iMX8X
C182 = 100nF,_10V,_X7R,_10%,_0402_8: CLABCONF0: = SB-iMX8X
C26 C57 C161 C183 = 100nF,_10V,_X7R,_10%,_0402_1: CLABCONF0: = SB-iMX8X
C184 = 100nF,_10V,_X7R,_10%,_0402_25: CLABCONF0: = SB-iMX8X
C185 = 100nF,_10V,_X7R,_10%,_0402_18: CLABCONF0: = SB-iMX8X
C186 C193 = 100nF,_10V,_X7R,_10%,_0402_10: CLABCONF0: = SB-iMX8X
C27 C58 C187 = 100nF,_10V,_X7R,_10%,_0402_3: CLABCONF0: = SB-iMX8X
C188 = 100nF,_10V,_X7R,_10%,_0402_26: CLABCONF0: = SB-iMX8X
C189 = 100nF,_10V,_X7R,_10%,_0402_20: CLABCONF0: = SB-iMX8X
C194 = 100nF,_10V,_X7R,_10%,_0402_12: CLABCONF0: = SB-iMX8X
C63 C136 C195 = 100nF,_10V,_X7R,_10%,_0402_4: CLABCONF0: = SB-iMX8X
C196 = 100nF,_10V,_X7R,_10%,_0402_28: CLABCONF0: = SB-iMX8X
C197 = 100nF,_10V,_X7R,_10%,_0402_22: CLABCONF0: = SB-iMX8X
C198 = 100nF,_10V,_X7R,_10%,_0402_14: CLABCONF0: = SB-iMX8X
C56 C199 = 100nF,_10V,_X7R,_10%,_0402_7: CLABCONF0: = SB-iMX8X
C200 = 100nF,_10V,_X7R,_10%,_0402_29: CLABCONF0: = SB-iMX8X
C205 = 100nF,_10V,_X7R,_10%,_0402_27: CLABCONF0: = SB-iMX8X
C206 = 100nF,_10V,_X7R,_10%,_0402_15: CLABCONF0: = SB-iMX8X
C207 = 100nF,_10V,_X7R,_10%,_0402_11: CLABCONF0: = SB-iMX8X
P1 = SODIMM-204_45: CLABCONF0: = SB-iMX8X; P/N: 190I20400S
R80 R95 R149 = 1K,1%,0402,1_16W: CLABCONF0: = SB-iMX8X; Group: CAN
C20 = 100nF,_10V,_X7R,_10%,_0402_3: CLABCONF0: = SB-iMX8X; Group: LAN2
C21 = 100nF,_10V,_X7R,_10%,_0402_2: CLABCONF0: = SB-iMX8X; Group: LAN2
C23 = 100nF,_10V,_X7R,_10%,_0402: CLABCONF0: = SB-iMX8X; Group: LAN2
C24 = 100nF,_10V,_X7R,_10%,_0402_1: CLABCONF0: = SB-iMX8X; Group: LAN2
D1 D2 = BAT54C: CLABCONF0: = SB-iMX8X
P2 = RJ45_1Gbit_SHORT_DOUBLE: CLABCONF0: = SB-iMX8X; Color: Default; Location X-Coordinate: 0; Location Y-Coordinate: 0; P/N: 182K02800; Power Pins Visible: False; Primitive: DEFAULT
R50 = 475R_1%,_0402_1: CLABCONF0: = SB-iMX8X
R51 R54 = 475R_1%,_0402: CLABCONF0: = SB-iMX8X
R52 = 475R_1%,_0402_3: CLABCONF0: = SB-iMX8X
R56 = 475R_1%,_0402_2: CLABCONF0: = SB-iMX8X
C64 C68 C70 C72 C160 = 10uF,6_0.3V,0603,20%X5R: CLABCONF0: = SB-iMX8X
F5 F6 = Fuse,_0.75A_Ih,_1.5A_It: CLABCONF0: = SB-iMX8X; P/N: 175P22200S
L6-L9 L14 L15 L47-L51 = ESD_CHOKE_DIFFx2_10: CLABCONF0: = SB-iMX8X; P/N: 142D11801S
P9 = USB3_OTGMINIB_5: CLABCONF0: = SB-iMX8X; P/N: 180K01000S
P10 = uSIM_SOCKET_0: CLABCONF0: = SB-iMX8X
P11 = mini_PCIe_0: CLABCONF0: = SB-iMX8X; P/N: 182K05201S
Q4 Q16 = N-MOSFET,NDS335N,100mOhm@2.5V: CLABCONF0: = SB-iMX8X
R35 R96 R105 = 10K,1%,0402,1_16W_1: CLABCONF0: = SB-iMX8X
R91 R155 = 10K,1%,0402,1_16W: CLABCONF0: = SB-iMX8X
R13 R92 = 100K,_0402: CLABCONF0: = SB-iMX8X; P/N: 161C10031S
R94 R204 = 0R,_0402_1: CLABCONF0: = SB-iMX8X
R108 = 49.9R_1%,_0402_1: CLABCONF0: = DNP
R109 = 49.9R_1%,_0402: CLABCONF0: = DNP
R128 R153 = 10K,1%,0402,1_16W_2: CLABCONF0: = SB-iMX8X
R145 R179 = 0R,_0402_1_1: CLABCONF0: = DNP
U9 = RYC8220-1M_DUAL_USB_PWR_SWITCH: CLABCONF0: = SB-iMX8X
U30 = USB_A-TYPE_DOUBLE_TH: CLABCONF0: = SB-iMX8X; Group: Front Panel
E6 E12 = HDR_1x2_100MIL_TH_JUMPER: CLABCONF0: = SB-iMX8X
JP1 JP6 JP11-JP15 = Jumper,_black,_100mil: CLABCONF0: = SB-iMX8X
JP2 = Jumper,_black,_100mil: CLABCONF0: = DNP
P20 P21 = HDR_2x17_100MIL_SMT: CLABCONF0: = SB-iMX8X
P29 = HDR_2x5_100MIL_TH: CLABCONF0: = SB-iMX8X; Group: COM2
R31 = 4_0.75K,1%,0402,1_16W_2: CLABCONF0: = DNP
R32 = 4_0.75K,1%,0402,1_16W_1: CLABCONF0: = DNP
R34 R43 = 4_0.75K,1%,0402,1_16W: CLABCONF0: = SB-iMX8X
R110 = 10K,1%,0402,1_16W_3: CLABCONF0: = SB-iMX8X
R138 = 49.9R_1%,_0402: CLABCONF0: = SB-iMX8X
R152 = 0R,_0402: CLABCONF0: = DNP
R93 R156 = 10K,1%,0402,1_16W_4: CLABCONF0: = SB-iMX8X
R83 R162 R243 = 0R,_0402_1: CLABCONF0: = DNP
SW4-SW6 = TACT_SW_6x6mm_SMT: CLABCONF0: = SB-iMX8X
C59 C61 = 1uF,X5R,6.3V,0402: CLABCONF0: = DNP
C363 = 100nF,_10V,_X7R,_10%,_0402_8: CLABCONF0: = SB-iMX8X; Group: CAN
C364 = 100nF,_10V,_X7R,_10%,_0402_2: CLABCONF0: = SB-iMX8X; Group: CAN
E11 = HDR_1x2_100MIL_TH_JUMPER_3: CLABCONF0: = SB-iMX8X
E13 = HDR_1x2_100MIL_TH_JUMPER_1: CLABCONF0: = SB-iMX8X
E14 = HDR_1x2_100MIL_TH_JUMPER_4: CLABCONF0: = SB-iMX8X
E15 = HDR_1x2_100MIL_TH_JUMPER_2: CLABCONF0: = SB-iMX8X
E16-E19 = HDR_2x4_100MIL_SMT_2: CLABCONF0: = SB-iMX8X
OSC1 = Osc.,_50Mhz,50PPM,_3.3V: CLABCONF0: = SB-iMX8X; P/N: 141C25601S
P8 = Conn_2x12_B2B_P_0.4mm_Socket: CLABCONF0: = SB-iMX8X; P/N: 182K02401S
P17 P18 = RJ11: CLABCONF0: = DNP
P27 P28 = HDR_2x4_100MIL_SMT: CLABCONF0: = SB-iMX8X
Q3 Q14 = N-MOSFET,NDS335N,100mOhm@2.5V: CLABCONF0: = DNP
R7 = 1K,1%,0402,1_16W_1: CLABCONF0: = SB-iMX8X; Group: CAN
R14 = 1K,1%,0402,1_16W_5: CLABCONF0: = SB-iMX8X; Group: CAN
R16 = 100K,_0402_1: CLABCONF0: = SB-iMX8X; P/N: 161C10031S
R33 R39 = 4_0.75K,1%,0402,1_16W_1: CLABCONF0: = SB-iMX8X
R73 = 10K,1%,0402,1_16W: CLABCONF0: = DNP
R74 R143 = 2.2K,5%,0402.1_16W: CLABCONF0: = DNP
R75 = 10K,1%,0402,1_16W_10: CLABCONF0: = DNP
R76 = 2.2K,5%,0402.1_16W_1: CLABCONF0: = DNP
R77 = 1K,1%,0402,1_16W_2: CLABCONF0: = SB-iMX8X; Group: CAN
R78 = 10K,1%,0402,1_16W_6: CLABCONF0: = SB-iMX8X
R79 = 10K,1%,0402,1_16W_2: CLABCONF0: = DNP
R81 = 0R,_0402_1_3: CLABCONF0: = SB-iMX8X
R82 = 100K,_0402_2: CLABCONF0: = DNP; P/N: 161C10031S
R84 = 0R,_0402_1_1: CLABCONF0: = SB-iMX8X
R85 = 0R,_0402_1_14: CLABCONF0: = DNP
R86 = 0R,_0402_1_5: CLABCONF0: = SB-iMX8X
R87 = 1K,1%,0402,1_16W_4: CLABCONF0: = DNP; Group: CAN
R88 = 0R,_0402_1_12: CLABCONF0: = SB-iMX8X
R89 = 10K,1%,0402,1_16W_7: CLABCONF0: = DNP
R90 = 0R,_0402_1_15: CLABCONF0: = DNP
R97 = 13.3K,_0402_tmp: CLABCONF0: = SB-iMX8X; P/N: 161C13321S
R98 = 10K,1%,0402,1_16W_12: CLABCONF0: = SB-iMX8X
R99 = 0R,_0402_1_7: CLABCONF0: = SB-iMX8X
R100 = 10K,1%,0402,1_16W_11: CLABCONF0: = SB-iMX8X
R101 = 10K,1%,0402,1_16W_8: CLABCONF0: = SB-iMX8X
R102 = 10K,1%,0402,1_16W_5: CLABCONF0: = SB-iMX8X; P/N: 161C16521S
R103 = 33R,5%,0402,1_16W: CLABCONF0: = SB-iMX8X; P/N: 161C64911S
R104 = 0R,_0402_1_8: CLABCONF0: = SB-iMX8X
R106 = 953R,1%,0402,1_16W_0: CLABCONF0: = SB-iMX8X; P/N: 161C91011S
R107 = 10K,1%,0402,1_16W_9: CLABCONF0: = SB-iMX8X
R136 = 0R,_0402_1_4: CLABCONF0: = DNP
R144 = 0R,_0402_1_17: CLABCONF0: = SB-iMX8X
R150 = 10K,1%,0402,1_16W_3: CLABCONF0: = DNP
R166 = 0R,_0402_1_6: CLABCONF0: = DNP
R167 = 0R,_0402_1_2: CLABCONF0: = DNP
R176 = 1K,1%,0402,1_16W_3: CLABCONF0: = SB-iMX8X; Group: CAN
R177 = 0R,_0402_1_11: CLABCONF0: = SB-iMX8X
R178 = 0R,_0402_1_9: CLABCONF0: = SB-iMX8X
R180 = 0R,_0402_1_10: CLABCONF0: = SB-iMX8X
R199 = 0R,_0402_1_16: CLABCONF0: = SB-iMX8X
R200 = 0R,_0402_1_13: CLABCONF0: = SB-iMX8X
R209 = 0R,_0402_1_18: CLABCONF0: = SB-iMX8X
R2004 = 120R_1%,_0603_1: CLABCONF0: = SB-iMX8X
R2005 = 120R_1%,_0603: CLABCONF0: = SB-iMX8X
RN17 = RN,10K,8P4R@0805: CLABCONF0: = SB-iMX8X
U8 = TXS0102_0: CLABCONF0: = SB-iMX8X; P/N: 116A01020S
U10-U12 = RT9186A,LDO_,2.5-5_0.5V,500mA: CLABCONF0: = SB-iMX8X
U31 = PCA9555: CLABCONF0: = SB-iMX8X
U35 U39 = AduM1201: CLABCONF0: = SB-iMX8X; Group: CAN
U38 U40 = TJA1050T: CLABCONF0: = SB-iMX8X; Group: CAN
C138 = 22uF,6.3V,X5R: CLABCONF0: = SB-iMX8X; P/N: 151B22610S
C278 = 1uF,X5R,6.3V,0402: CLABCONF0: = SB-iMX8X; P/N: 151D10510S
D3 = BAT54WS_0: CLABCONF0: = SB-iMX8X
D9 = ZENER_24V_500mW_SOD-123: CLABCONF0: = DNP
L13 = INC_DELTA_SI43-100,_10uH: CLABCONF0: = SB-iMX8X; CLABCONF1: <null>; CLABCONF2: <null>; CLABCONF3: <null>; CLABCONF4: <null>; CLABCONF5: <null>; CLABCONF6: <null>; CLABCONF7: <null>; CLABCONF8: <null>; CLABCONF9: <null>
P22 = FPC_Connector_30: CLABCONF0: = SB-iMX8X; P/N: 182P03002S
P46 = FPC_Connector_8: CLABCONF0: = SB-iMX8X; P/N: 182P00802S
P47 = QSH-030-01-F-D-A: CLABCONF0: = SB-iMX8X; P/N: 182K06003S
R36 = 2.2R,5%,0402,1_16W_1: CLABCONF0: = SB-iMX8X; P/N: 161C00005S
R37 = 4_0.75K,1%,0402,1_16W: CLABCONF0: = DNP
R40 = 4_0.75K,1%,0402,1_16W_2: CLABCONF0: = SB-iMX8X
R41 = 2.2R,5%,0402,1_16W: CLABCONF0: = SB-iMX8X; P/N: 161C06R25S
R42 = 0R,_0402_10: CLABCONF0: = SB-iMX8X
R142 = 0R,_0402_7: CLABCONF0: = SB-iMX8X
R147 = 0R,_0402_16: CLABCONF0: = SB-iMX8X
R148 = 0R,_0402_15: CLABCONF0: = DNP
R208 = 0R,_0402_9: CLABCONF0: = SB-iMX8X
R211 = 0R,_0402_6: CLABCONF0: = DNP
R212 = 0R,_0402_5: CLABCONF0: = DNP
R215 = 0R,_0402_0: CLABCONF0: = DNP; P/N: 161C00005S
R229 = 0R,_0402_14: CLABCONF0: = SB-iMX8X
R231 = 0R,_0402_3: CLABCONF0: = SB-iMX8X
R232 = 0R,_0402_12: CLABCONF0: = SB-iMX8X
R233 = 0R,_0402_2: CLABCONF0: = SB-iMX8X
R234 = 0R,_0402_11: CLABCONF0: = SB-iMX8X
R240 = 0R,_0402: CLABCONF0: = SB-iMX8X
R241 = 0R,_0402_8: CLABCONF0: = SB-iMX8X
R242 = 0R,_0402_4: CLABCONF0: = DNP
R244 = 10K,1%,0402,1_16W_0: CLABCONF0: = SB-iMX8X
R245 = 0R,_0402_13: CLABCONF0: = DNP
TP3 = TESTPOINT: CLABCONF0: = DNP
U20 = AIC1647_0: CLABCONF0: = SB-iMX8X; P/N: 123C40000S
U33 = IP4220CZ6_0: CLABCONF0: = SB-iMX8X
H7-H11 = Mechanical_Hole: CLABCONF0: = DNP
H12 = Hole,_Plated,_M2,_5mm._ext.: CLABCONF0: = DNP
SCREW1 = SCREW,_M2,_3.5mm,_PAN_HEAD: CLABCONF0: = SB-iMX8X
SP10 SP21 SP22 = SMT_SPACER_M2x3_1: CLABCONF0: = SB-iMX8X
SPACER1 = Hexagonal_Standoff_0: CLABCONF0: = DNP; P/N: 206C10160

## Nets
3V3_AW: C74.1 C193.1 C363.1 C364.1 P11.24(+3.3V_AUX) P21.7 R13.1 R16.1 R33.1 R34.1 R35.1 R136.2 R166.2 R167.2 SW6.1 SW6.3 U31.21(VDD) U35.1(VCC1) U39.1(VCC1) ; also on sheet 9 10
3V3_PER: C26.1 C54.1 C73.1 C75.1 C192.2 C208.1 C209.1 C210.1 C211.1 P11.2(+3.3V_1) P11.39(RSVD6) P11.41(RSVD7) P11.52(+3.3V_2) P21.6 P47.36 R31.1 R32.1 R39.1 R40.1 R84.1 R91.1 R92.2 R128.1 R142.1 R147.2 R149.2 R152.2 R212.2 R229.1 U8.7(VCCB) ; also on sheet 9 10
3V3_PER_R: P1.196(BOOT_PWR_IN) R149.1
5V0_PER: C25.1 C160.1 C161.1 E11.2 E13.2 F5.2 F6.2 P21.12 P47.21 P47.23 U9.7(VCC) ; also on sheet 10
AGND: P1.195(ANALOG_GND) P21.29 R179.2
GND: C1.2 C2.2 C3.2 C4.2 C5.2 C6.2 C7.2 C8.2 C9.2 C10.2 C11.2 C12.2 C13.2 C14.2 C15.2 C16.2 C17.2 C18.2 C19.2 C20.2 C21.2 C22.2 C23.2 C24.2 C25.2 C26.2 C27.2 C54.2 C55.2 C56.1 C57.2 C58.2 C59.2 C60.2 C61.1 C62.1 C63.2 C64.2 C65.2 C66.2 C67.2 C68.2 C69.2 C70.2 C71.2 C72.2 C73.2 C74.2 C75.2 C80.2 C81.2 C82.2 C136.2 C138.2 C140.1 C141.1 C160.2 C161.2 C170.1 C171.1 C172.1 C173.1 C174.1 C175.1 C176.1 C177.1 C178.1 C179.1 C180.1 C181.1 C182.1 C183.1 C184.1 C185.1 C186.1 C187.1 C188.1 C189.1 C190.2 C191.2 C192.1 C193.2 C194.1 C195.1 C196.1 C197.1 C198.1 C199.1 C200.1 C205.1 C206.1 C207.1 C208.2 C209.2 C210.2 C211.2 C278.2 C363.2 C364.2 E12.2 E14.2 E16.3 E17.1 E18.3 E19.1 H7.1 H8.1 H9.1 H10.1 H11.1 H12.1 L6.5(GND) L6.6(GND) L7.5(GND) L7.6(GND) L8.5(GND) L8.6(GND) L9.5(GND) L9.6(GND) L14.5(GND) L14.6(GND) L15.5(GND) L15.6(GND) L47.5(GND) L47.6(GND) L48.5(GND) L48.6(GND) L49.5(GND) L49.6(GND) L50.5(GND) L50.6(GND) L51.5(GND) L51.6(GND) OSC1.2(GND) P1.1(GND1) P1.19(GND2) P1.37(GND3) P1.55(GND4) P1.71(GND5) P1.87(GND6) P1.105(GND7) P1.123(GND8) P1.141(GND9) P1.159(GND10) P1.177(GND11) P2.S1(SHIELD) P2.S2(SHIELD) P8.2(AGND) P8.15(DGND) P8.24(AF_GND) P9.5(GND) P9.8(GNDD) P9.NC1(CHASSIS) P9.NC2(CHASSIS) P9.NC3(CHASSIS) P9.NC4(CHASSIS) P9.NC5(CHASSIS) P9.NC6(CHASSIS) P10.5(GND) P10.9(M9) P10.10(M10) P10.11(M11) P10.12(M12) P11.4(GND7) P11.9(GND1) P11.15(GND2) P11.18(GND8) P11.21(GND3) P11.26(GND9) P11.27(GND4) P11.29(GND5) P11.34(GND10) P11.35(GND6) P11.37(RSVD5) P11.40(GND11) P11.50(GND12) P17.2 P17.5 P18.2 P18.5 P20.33 P21.31 P22.6 P22.9 P22.12 P22.15 P22.18 P22.21 P22.22 P22.24 P22.29 P22.30 P27.2 P27.7 P28.1 P28.4 P28.5 P28.8 P29.4 P29.6 P47.1 P47.6 P47.7 P47.12 P47.13 P47.18 P47.19 P47.61 P47.62 P47.63 P47.64 Q3.2(S) Q4.2(S) Q14.2(S) Q16.2(S) R36.2 R43.1 R50.2 R51.2 R52.2 R54.2 R56.2 R75.1 R77.1 R80.1 R87.2 R89.1 R98.2 R103.1 R107.2 R108.2 R109.2 R143.2 R156.2 R162.1 R179.1 R234.1 R241.1 RN17.2(RB1) RN17.3(RC1) RN17.4(RD1) SP10.1 SP21.1 SP22.1 SW4.1 SW4.3 SW5.1 SW5.3 U8.2(GND) U9.6(GND) U10.5(GND) U10.9(EPAD) U11.5(GND) U11.9(EPAD) U12.5(GND) U12.9(EPAD) U20.2(GND) U30.4(GND) U30.8(GND) U30.9(SHIELD) U30.10(SHIELD) U30.11(SHIELD) U30.12(SHIELD) U31.9(VSS) U35.4(GND1) U39.4(GND1) ; also on sheet 9 10
VBUS_OTG: C64.1 C65.1 C66.1 P9.1(5VUSB) R95.2 U9.8(OUT_A)
VCC_RTC: C1.1 P1.183(BACKUP_BAT) ; also on sheet 10
ADC_IN0: P1.191(ANALOG_IN0) P21.19
ADC_IN1: P1.193(ANALOG_IN1) P21.21
ADC_IN2: P1.197(ANALOG_IN2) P21.23
ADC_IN3: P1.199(ANALOG_IN3) P21.25
ADC_IN4: P1.201(ANALOG_IN4) P21.27
ALT_BOOT: P1.185(ALT_BOOT) P21.8 Q16.1(G) SW6.2 SW6.4
BCKLIGHT_FB: D9.2(ANODE) R42.2 U20.3(FB)
CAM_SCCB_EN: C59.1 R78.2 U8.6(OE)
CAN0_GND: E12.1 E17.3 P17.6 R7.1 U35.5(GND2) U38.2(GND)
CAN0_H: E16.2 P17.3 R2004.1 U38.7(CANH)
CAN0_L: E17.2 P17.4 R2004.2 U38.6(CANL)
CAN0_RX: P1.108(CAN0_RX) U35.2(OUTA)
CAN0_STB_PD: R7.2 U38.8(S)
CAN0_TX: P1.110(CAN0_TX) R13.2 U35.3(INB)
CAN0_VCC: E11.1 E16.1 P17.1 U35.8(VCC2) U38.3(VCC)
CAN2_GND: E14.1 E19.3 P18.6 R14.1 U39.5(GND2) U40.2(GND)
CAN2_H: E18.2 P18.3 R2005.1 U40.7(CANH)
CAN2_L: E19.2 P18.4 R2005.2 U40.6(CANL)
CAN2_RX: P1.126(CAN2_RX) U39.2(OUTA)
CAN2_STB_PD: R14.2 U40.8(S)
CAN2_TX: P1.128(CAN2_TX) R16.2 U39.3(INB)
CAN2_VCC: E13.1 E18.1 P18.1 U39.8(VCC2) U40.3(VCC)
CARRIER_3V3_GPIO0_2: R144.2 U31.3(I/O0.2)
CARRIER_3V3_GPIO0_5: R176.1 U31.6(I/O0.5)
CARRIER_3V3_GPIO0_6: R177.2 U31.7(I/O0.6)
CARRIER_3V3_GPIO0_7: R180.2 U31.8(I/O0.7)
CARRIER_3V3_GPIO1_0: R178.2 U31.10(I/O1.0)
CARRIER_3V3_GPIO1_1: R200.2 U31.11(I/O1.1)
CARRIER_3V3_GPIO1_2: R199.2 U31.12(I/O1.2)
CARRIER_3V3_GPIO1_4: R209.2 U31.14(I/O1.4)
CARRIER_I2C_SCL_1V8: P8.5(SCL) R76.1 U8.4(A2)
CARRIER_I2C_SDA_1V8: P8.3(SDA) R74.1 U8.5(A1)
CEC_CLK: P20.32 P47.45
CEC_IO: P20.34 P47.47
COLD_RESET_IN: P1.171(COLD_RESET_IN) P20.28 SW5.2 SW5.4
CONN_CAM_CLK: P8.13(XCLK) R83.2 R86.2 R87.1
CSI0_CLKN: P1.109(CSI0_CLKN) P8.18(MCN)
CSI0_CLKP: P1.107(CSI0_CLKP) P8.16(MCP)
CSI0_DN0: P1.85(CSI0_DN0) P8.22(MDN0)
CSI0_DN1: P1.91(CSI0_DN1) P8.14(MDN1)
CSI0_DN2: P1.103(CSI0_DN2) P27.3
CSI0_DN3: P1.113(CSI0_DN3) P27.4
CSI0_DP0: P1.83(CSI0_DP0) P8.20(MDP0)
CSI0_DP1: P1.89(CSI0_DP1) P8.12(MDP1)
CSI0_DP2: P1.101(CSI0_DP2) P27.5
CSI0_DP3: P1.115(CSI0_DP3) P27.6
CSI0_GPIO2: P1.167(CSI0_GPIO2) P27.1
CSI0_GPIO3: P1.169(CSI0_GPIO3) P27.8
CSI0_MCLK: P1.175(CSI0_MCLK) R83.1
CSI_PWR_DWN: P8.8(PWDN) Q3.3(D) R79.1 R80.2 R178.1
CSI_RST: P8.6(RESET) R77.2 R180.1
CSTRB: P8.1(STROBE) R73.2 R75.2
DBG_UART_RXD: P1.117(UARTDBG_RX) ; also on sheet 9
DBG_UART_TXD: P1.111(UARTDBG_TX) ; also on sheet 9
DEBUGSEL: R176.2 ; also on sheet 9
DISP_IO: C140.2 C190.1 P22.27 R147.1 R148.2
DISP_PWR: C141.2 C191.1 P22.28 R142.2
DISP_RESET: P22.26 R209.1 R215.1 R240.1
DSI0_CLKN: P1.35(DSI0_CLKN) P47.5
DSI0_CLKP: P1.33(DSI0_CLKP) P47.3
DSI0_I2C_SCL: P1.43(DSI0_I2C_SCL) P47.44
DSI0_I2C_SDA: P1.49(DSI0_I2C_SDA) P47.40
DSI0_INT: P1.74(DSI0_INT) P47.4
DSI0_TX0N: P1.41(DSI0_TX0N) P47.11
DSI0_TX0P: P1.39(DSI0_TX0P) P47.9
DSI0_TX1N: P1.47(DSI0_TX1N) P47.17
DSI0_TX1P: P1.45(DSI0_TX1P) P47.15
DSI0_TX2N: P1.53(DSI0_TX2N) P47.10
DSI0_TX2P: P1.51(DSI0_TX2P) P47.8
DSI0_TX3N: P1.59(DSI0_TX3N) P47.16
DSI0_TX3P: P1.57(DSI0_TX3P) P47.14
DSI1_CLKN: L48.3 P1.79(DSI1_CLKN)
DSI1_CLKP: L48.4 P1.77(DSI1_CLKP)
DSI1_I2C_SCL: P1.151(DSI1_I2C_SCL) R39.2 R231.1
DSI1_I2C_SDA: P1.153(DSI1_I2C_SDA) R40.2 R232.1
DSI1_INT: P1.27(DSI1_INT) R233.1
DSI1_PWM: P1.29(DSI1_PWM) R211.1
DSI1_TX0N: L51.3 P1.23(DSI1_TX0N)
DSI1_TX0P: L51.4 P1.21(DSI1_TX0P)
DSI1_TX1N: L47.3 P1.95(DSI1_TX1N)
DSI1_TX1P: L47.4 P1.93(DSI1_TX1P)
DSI1_TX2N: L49.3 P1.157(DSI1_TX2N)
DSI1_TX2P: L49.4 P1.155(DSI1_TX2P)
DSI1_TX3N: L50.3 P1.163(DSI1_TX3N)
DSI1_TX3P: L50.4 P1.161(DSI1_TX3P)
DSI_CLN: L48.2 P22.13
DSI_CLP: L48.1 P22.14
DSI_N0: L51.2 P22.7
DSI_N1: L47.2 P22.10
DSI_N2: L49.2 P22.16
DSI_N3: L50.2 P22.19
DSI_P0: L51.1 P22.8
DSI_P1: L47.1 P22.11
DSI_P2: L49.1 P22.17
DSI_P3: L50.1 P22.20
EEPROM_WP: P1.189(EEPROM_WP) P21.32
ETH1_CT1: C19.1 C20.1 P2.A5(CT1)
ETH1_CT2: C23.1 P2.A6(CT2)
ETH1_GREEN_LED_CAT: P2.A11(LED1_C) R50.1
ETH1_LED_ACT/PHY1ADDRESS2: P1.4(ETH1_LED2_ACT) P2.A12(LED1_A)
ETH1_LINK-LED_10_100: D1.1(ANODE1) P1.22(ETH1_LED3_10_100)
ETH1_LINK-LED_1000/INTSELECT: D1.2(ANODE2) P1.16(ETH1_LED1_1000)
ETH1_MDI0N: P1.6(ETH1_MDI0N) P2.A2(MDI0-)
ETH1_MDI0P: P1.8(ETH1_MDI0P) P2.A1(MDI0+)
ETH1_MDI1N: P1.12(ETH1_MDI1N) P2.A4(MDI1-)
ETH1_MDI1P: P1.14(ETH1_MDI1P) P2.A3(MDI1+)
ETH1_MDI2N: P1.18(ETH1_MDI2N) P2.A8(MDI2-)
ETH1_MDI2P: P1.20(ETH1_MDI2P) P2.A7(MDI2+)
ETH1_MDI3N: P1.24(ETH1_MDI3N) P2.A10(MDI3-)
ETH1_MDI3P: P1.26(ETH1_MDI3P) P2.A9(MDI3+)
ETH1_TXD2_BYP: P1.62(ETH1_TXD2_BYP) P20.1
ETH1_YELLOW_LED_AN: D1.3(CATHODE) P2.A14(LED2_A)
ETH1_YELLOW_LED_CAT: P2.A13(LED2_C) R51.1
ETH2_BYP_RXC: P1.31(ETH2_BYP_RXC) P20.3
ETH2_CT1: C21.1 C22.1 P2.B5(CT1)
ETH2_CT2: C24.1 P2.B6(CT2)
ETH2_GREEN_LED_CAT: P2.B11(LED1_C) R52.1
ETH2_LED_ACT/PHY2ADDRESS2: P1.25(ETH2_LED5_ACT) P2.B12(LED1_A)
ETH2_LINK-LED_10_100: D2.1(ANODE1) P1.34(ETH2_LED6_10_100)
ETH2_LINK-LED_1000/INTSELECT2: D2.2(ANODE2) P1.40(ETH2_LED4_1000)
ETH2_MDI0N: P1.30(ETH2_MDI0N) P2.B2(MDI0-)
ETH2_MDI0P: P1.32(ETH2_MDI0P) P2.B1(MDI0+)
ETH2_MDI1N: P1.36(ETH2_MDI1N) P2.B4(MDI1-)
ETH2_MDI1P: P1.38(ETH2_MDI1P) P2.B3(MDI1+)
ETH2_MDI2N: P1.42(ETH2_MDI2N) P2.B8(MDI2-)
ETH2_MDI2P: P1.44(ETH2_MDI2P) P2.B7(MDI2+)
ETH2_MDI3N: P1.48(ETH2_MDI3N) P2.B10(MDI3-)
ETH2_MDI3P: P1.50(ETH2_MDI3P) P2.B9(MDI3+)
ETH2_YELLOW_LED_AN: D2.3(CATHODE) P2.B14(LED2_A)
ETH2_YELLOW_LED_CAT: P2.B13(LED2_C) R56.1
EXPANDER_A0: R166.1 RN17.5(RD2) U31.18(A0)
EXPANDER_A1: R167.1 RN17.6(RC2) U31.23(A1)
EXPANDER_A2: R136.1 RN17.7(RB2) U31.24(A2)
FB_LDO_1V5: R106.1 R107.1 U12.6(ADJ)
FB_LDO_1V8: R97.1 R98.1 U10.6(ADJ)
FB_LDO_2V8: R102.1 R103.2 U11.6(ADJ)
FPC_GND: P46.1 P46.8 R234.2 R241.2 U33.2(GND)
FPC_INT: P46.6 R233.2 R242.2 U33.3(IO2)
FPC_RES#: P46.7 R240.2 R243.2 U33.1(IO1)
FPC_SCL: P46.4 R231.2 U33.4(IO3)
FPC_SDA: P46.5 R232.2 U33.6(IO4)
FPC_VDD: P46.3 R229.2 U33.5(VBUS)
GPIO1: P1.152(GPIO1) P21.1
GPIO_012: P1.200(GPIO_012) P21.3
GPIO_019: P1.146(GPIO_019) P20.24
GPIO_020: P1.148(GPIO_020) P20.26
GPIO_301: P1.112(GPIO_301) P20.7
GPIO_313: P1.130(GPIO_313) P20.2
GPIO_317: P1.92(GPIO_317) P21.15
GPIO_318: P1.94(GPIO_318) P21.17
I2C0_SCL: P1.73(I2C0_SCL) P20.6 R31.2
I2C0_SDA: P1.75(I2C0_SDA) P20.8 R32.2
I2C3_SCL: P1.179(I2C3_SCL) P20.10
I2C3_SDA: P1.181(I2C3_SDA) P20.12
I2S1_CLKX: P1.137(I2S1_CLKX) P28.2 P47.35
I2S1_DIN: P1.143(I2S1_DIN) P28.3
I2S1_DOUT: P1.139(I2S1_DOUT) P28.7 P47.39
I2S1_FSX: P1.145(I2S1_FSX) P28.6 P47.37
JTAG_HDR_10: P29.10 R162.2
JTAG_nRST: P1.56(JTAG_nTRST) P29.9 R155.2
JTAG_TCK: P1.66(JTAG_TCK) P29.3 R156.1
JTAG_TDI: P1.70(JTAG_TDI) P29.7 R153.2
JTAG_TDO: P1.72(JTAG_TDO) P29.5
JTAG_TMS: P1.68(JTAG_TMS) P29.1 R110.2
JTAG_VCC: P29.2 R110.1 R138.1 R152.1 R153.1 R155.1
LCD_INT_GPIO: R200.1 R242.1
LCD_LED_GPIO: R199.1 R245.1
LED_A: C278.1 D3.CATHODE D9.1(CATHODE) P22.4 U20.5(OVP)
LED_EN: R211.2 R244.2 R245.2 U20.4(EN/PWM)
LED_K: P22.2 R41.1 R42.1
MCLK_VCC: C63.1 OSC1.4(VCC) R84.2 R85.2
MIPICAM_DVDD1V5: C60.1 P8.10(DVDD1.5V) R81.1
mPCIE_CLK_REQn: P1.173(PCIE_CLK_REQn) P11.7(CLKREQ#)
mPCIE_REF_CLKN: P1.121(PCIE_REFCLK-) P11.11(REFCLK-) R108.1
mPCIE_REF_CLKP: P1.119(PCIE_REFCLK+) P11.13(REFCLK+) R109.1
mPCIE_RSTn: P1.192(PCIE_RSTn) P11.22(PERST#)
mPCIE_RXN: P1.133(PCIE_RX-) P11.23(PER_N0)
mPCIE_RXP: P1.131(PCIE_RX+) P11.25(PER_P0)
mPCIE_TXN: P1.127(PCIE_TX-) P11.31(PET_N0)
mPCIE_TXP: P1.125(PCIE_TX+) P11.33(PET_P0)
mPCIE_USB_DN: L9.3 P11.36(USB_D-)
mPCIE_USB_DP: L9.4 P11.38(USB_D+)
mPCIE_WAKEn: P1.194(PCIE_WAKEn) P11.1(WAKE#) R35.2
OSC25MHZ: OSC1.3(OUT) R86.1
OSCEN: OSC1.1(EN) R88.1 R89.2 R90.1
OTG_DN: L6.2 P9.2(D-)
OTG_DP: L6.1 P9.3(D+)
PCIE0_DEV_SEL: E15.2 P1.81(PCIE0_DEV_SEL) R144.1
PCIE0_DEV_SEL_J: E15.1 R54.1
PMIC_ON_REQ: P1.202(PER_PWREN_REQ) P20.4 R150.1 U10.4(EN) ; also on sheet 10
PMIC_STBY_REQ: P1.147(PMIC_STANDBY) P21.13
POR_B: P1.198(POR_RESET_3P3) P20.30 Q14.1(G) R204.1 R215.2 R243.1
POR_B#: P47.57 Q14.3(D) R37.2 R143.1 R204.2
PWDN_CAM_DLY: C61.2 Q3.1(G) R82.2
PWRBTN: P1.165(PWRON) P20.31 SW4.2 SW4.4
QSPI_BOOT: E6.2 P1.149(QSPI_BOOT) Q16.3(D)
QSPI_J: E6.1 R96.2
RS485_CTRL: R177.1 ; also on sheet 9
RSVD144: P1.144(RSVD144) P21.34
RTCK: P29.8 R43.2
RXD0_OUTB: U35.6(OUTB) U38.1(TxD)
RXD2_OUTB: U39.6(OUTB) U40.1(TxD)
SIM1_CLK: P10.3(CLK) P11.12(UIM_CLK)
SIM1_IO: P10.7(IO) P11.10(UIM_DATA)
SIM1_RST: P10.2(RST) P11.14(UIM_RESET)
SIM1_VCC: P10.1(VCC) P11.8(UIM_PWR)
SIM1_VPP: P10.6(VPP) P11.16(UIM_VPP)
SPI1_CLK: P1.98(SPI1_CLK) P20.18
SPI1_CS0: P1.104(SPI1_CS0) P20.14
SPI1_CS1: P1.106(SPI1_CS1) P20.16
SPI1_SIMO: P1.100(SPI1_SIMO) P20.22
SPI1_SOMI: P1.102(SPI1_SOMI) P20.20
SPI2_CLK: P1.116(SPI2_CLK) P21.26
SPI2_CS0: P1.122(SPI2_CS0) P21.22
SPI2_CS1: P1.124(SPI2_CS1) P21.24
SPI2_SIMO: P1.118(SPI2_SIMO) P21.30
SPI2_SOMI: P1.120(SPI2_SOMI) P21.28
SPI3_CLK: P1.134(SPI3_CLK) P20.25
SPI3_CS0: P1.140(SPI3_CS0) P20.21
SPI3_CS1: P1.142(SPI3_CS1) P20.23
SPI3_SIMO: P1.136(SPI3_SIMO) P20.29
SPI3_SOMI: P1.138(SPI3_SOMI) P20.27
SPI_CLK: P1.69(SPI_CLK) P21.14
SPI_CS0: P1.58(SPI_CS0) P21.2
SPI_CS1: P1.60(SPI_CS1) P21.4
SPI_SIMO: P1.65(SPI_SIMO) P21.20
SPI_SOMI: P1.63(SPI_SOMI) P21.16
SSUSB_RX_N: L8.3 P1.184(SSUSB_RXN)
SSUSB_RX_P: L8.4 P1.182(SSUSB_RXP)
SSUSB_TX_N: L7.3 P1.190(SSUSB_TXN)
SSUSB_TX_P: L7.4 P1.188(SSUSB_TXP)
SW_3P3_ON: P1.203(ANALOG_NC) ; also on sheet 10
SYS_I2C_SCL: P1.129(SYS_I2C_SCL) P11.30(SMB_CLK) R33.2 U8.1(B2) U31.19(SCL) ; also on sheet 9
SYS_I2C_SDA: P1.135(SYS_I2C_SDA) P11.32(SMB_DATA) R34.2 U8.8(B1) U31.20(SDA) ; also on sheet 9
TAMPER_IN: P1.99(TAMPER_IN) P21.9
TAMPER_OUT: P1.187(TAMPER_OUT) P21.11
TP3: P22.25 TP3.1
TXD0_INA: U35.7(INA) U38.4(RxD)
TXD2_INA: U39.7(INA) U40.4(RxD)
UART1_CTS: P1.15(UART1_CTS) P20.17
UART1_RTS: P1.17(UART1_RTS) P20.19
UART1_RX: P1.13(UART1_RX) P20.15
UART1_TX: P1.11(UART1_TX) P20.13
UART2_RX: P1.5(UART2_RX) ; also on sheet 9
UART2_TX: P1.3(UART2_TX) ; also on sheet 9
UART3_RX: P1.9(UART3_RX) P20.11 ; also on sheet 9
UART3_TX: P1.7(UART3_TX) P20.9 ; also on sheet 9
USB1_VBUS_EN: Q4.3(D) R91.2 R145.1 U9.1(EN_A)
USB_2_DN: L14.2 U30.2(D-)
USB_2_DP: L14.1 U30.3(D+)
USB_3_DN: L15.2 U30.6(D-)
USB_3_DP: L15.1 U30.7(D+)
USB_HUB1_DN: L9.2 P1.170(HSUSB1_DN)
USB_HUB1_DP: L9.1 P1.172(HSUSB1_DP)
USB_HUB2_DN: L14.3 P1.164(HSUSB2_DN)
USB_HUB2_DP: L14.4 P1.166(HSUSB2_DP)
USB_HUB3_DN: L15.3 P1.158(HSUSB3_DN)
USB_HUB3_DP: L15.4 P1.160(HSUSB3_DP)
USB_ID_CONN: P9.4(ID) Q4.1(G) R92.1 R94.1
USB_nOVC: P1.162(USB_nOVC) R128.2 U9.2(FLG_A)
USB_OTG2_DN: L6.3 P1.178(HSUSB0_DN)
USB_OTG2_DP: L6.4 P1.176(HSUSB0_DP)
USB_OTG_ID: P1.174(USBOTG_ID) R94.2
USB_OTG_VBUS_DET: P1.180(USBOTG_VBUS) R95.1
USB_PWREN: P1.156(USB_PWREN) R145.2
USB_VCC3: F5.1 U30.1(VBUS)
USB_VCC4: F6.1 U30.5(VBUS)
USBSS_RXN_CON: L8.2 P9.9(RX-)
USBSS_RXP_CON: L8.1 P9.10(RX+)
USBSS_TXN_CON: L7.2 P9.6(TX-)
USBSS_TXP_CON: L7.1 P9.7(TX+)
USDHC1_CLK: P1.80(SDCARD_CLK) ; also on sheet 9
USDHC1_CMD: P1.82(SDCARD_CMD) ; also on sheet 9
USDHC1_DATA0: P1.84(SDCARD_DAT0) ; also on sheet 9
USDHC1_DATA1: P1.86(SDCARD_DAT1) ; also on sheet 9
USDHC1_DATA2: P1.88(SDCARD_DAT2) ; also on sheet 9
USDHC1_DATA3: P1.90(SDCARD_DAT3) ; also on sheet 9
USDHC1_nCD: P1.61(SDCARD_CD) ; also on sheet 9
USDHC1_nRST: P1.154(SDCARD_RST) P20.5
USDHC1_WP: P1.67(SDCARD_WP) ; also on sheet 9
V_LED: C136.1 C138.1 L13.1 R208.2 R212.1 R244.1 U20.6(IN)
V_SOM: C2.1 C3.1 C4.1 C5.1 C6.1 C7.1 C8.1 C9.1 C10.1 C11.1 C12.1 C13.1 C14.1 C15.1 C16.1 C17.1 C18.1 C67.1 C69.1 C71.1 C170.2 C171.2 C172.2 C173.2 C174.2 C175.2 C176.2 C177.2 C178.2 C179.2 C180.2 C181.2 C182.2 C183.2 C184.2 C185.2 C186.2 C187.2 C188.2 C189.2 C194.2 C195.2 C196.2 C197.2 C198.2 C199.2 C200.2 C205.2 C206.2 C207.2 P1.10(VSYS1) P1.28(VSYS2) P1.46(VSYS3) P1.64(VSYS4) P1.78(VSYS5) P1.96(VSYS6) P1.114(VSYS7) P1.132(VSYS8) P1.150(VSYS9) P1.168(VSYS10) P1.186(VSYS11) P1.204(VSYS12) R100.2 R105.2 R150.2 R208.1 U10.1(Vin1) U10.2(Vin2) U11.1(Vin1) U11.2(Vin2) U12.1(Vin1) U12.2(Vin2) ; also on sheet 10
V_SOM_EN: P21.33 ; also on sheet 10
VSB_1V5: C72.1 C80.1 C81.1 C82.1 P11.6(+1.5V_1) P11.28(+1.5V_2) P11.48(+1.5V_3) R81.2 R106.2 U12.7(Vout1) U12.8(Vout2)
VSB_1V5_EN: R104.2 R105.1 U12.4(EN)
VSB_1V8: C27.1 C55.1 C62.2 C68.1 P8.11(DVDD1.8V/2.8V) P21.18 P47.60 R37.1 R74.2 R76.2 R78.1 R79.2 R85.1 R90.2 R93.1 R96.1 R97.2 R138.2 R148.1 U8.3(VCCA) U10.7(Vout1) U10.8(Vout2)
VSB_1V8_PGOOD: R93.2 R99.2 U10.3(PGOOD)
VSB_2V8: C56.2 C57.1 C58.1 C70.1 P8.4(AVDD) P8.23(AF-VCC2.8V) R73.1 R82.1 R88.2 R101.1 R102.2 U11.7(Vout1) U11.8(Vout2)
VSB_2V8_EN: R99.1 R100.1 U11.4(EN)
VSB_2V8_PGOOD: R101.2 R104.1 U11.3(PGOOD)
WLD_RES: R36.1 R41.2
WLD_SW: D3.ANODE L13.2 U20.1(LX)

Not connected (* = marked no-connect by the designer): FID1 1*; FID2 1*; FID3 1*; FID4 1*; FID5 1*; FID6 1*; P1 2(PHY0_VDDH)* 52(ETH_MDC)* 54(PHY1_VDDH)* 76(DSI0_PWM)* 97(ETH_MDIO)*; P8 7(NC)* 9(NC)* 17(NC)* 19(NC)* 21(NC)*; P10 4(RSVD4)* 8(RSVD8)*; P11 3(RSVD1)* 5(RSVD2)* 17(RSVD3)* 19(RSVD4)* 20(RSVD18)* 42(LED_WWAN#)* 43(RSVD8)* 44(LED_WLAN#)* 45(RSVD9)* 46(LED_WPAN#)* 47(RSVD10)* 49(RSVD11)* 51(RSVD12)*; P21 5* 10*; P22 1* 3* 5* 23*; P46 2*; P47 2* 20* 22* 24* 25* 26* 27* 28* 29* 30* 31* 32* 33* 34* 38* 41* 42* 43* 46* 48* 49* 50* 51* 52* 53* 54* 55* 56* 58* 59*; RN17 1(RA1)* 8(RA2)*; U9 3(FLG_B)* 4(EN_B)* 5(OUT_B)*; U12 3(PGOOD)*; U31 1(I/O0.0)* 2(I/O0.1)* 4(I/O0.3)* 5(I/O0.4)* 13(I/O1.3)* 15(I/O1.5)* 16(I/O1.6)* 17(I/O1.7)* 22(\\~{IN}T)*; U38 5(Vref)*; U40 5(Vref)*

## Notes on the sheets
sheet 1
- LCD
- TFT
- MIPI-DSI CONN
- place P22-27 not too far from VSB_1V8
- diff 100 ohm
- diff 100 ohm
- diff 100 ohm
- diff 100 ohm
- diff 100 ohm
- diff 100 ohm
- diff 100 ohm
- diff 100 ohm
- diff 100 ohm
- diff 100 ohm
- TE
- RESET
- IOVCC
- VCI
- DNP
- DNP
- DNP
- DNP
- Polarity
  inversion
  provision
- I2S HEADER
- place P28 near P47
- DNP
- Touchscreen
- White LED Driver
- Typical LED configuration: Two parallel chains of 6 serially connected LEDs
- DNP
- I2C for touchscreen
- DNP
- DNP
- I2C addres:0xBA/0xBB or 0x28/0x29
- DNP
- provision
- DNP
sheet 2
- SODIMM SPACERS
- mPCIe SPACER
- DNP
- SB-iMX8 SPACERS
sheet 3
- Block Diagram
- SB-iMX8X
- BOARD REVISION: 1.0
- I2C ADDRESSES
- PAGE
- FUNCTION
- 01
- INDEX & BLOCK DIAGRAM
- DEVICE
- ADDRESS
- 02
- CARRIER BOARD INTERFACE
- EEPROM
- 0x54..57
- 03
- ETHERNET
- GPIO EXT
- 0x20
- 04
- USB OTG,USB DUAL CONN,mPCIe
- 05
- 100 MIL CONN
- 06
- CSI, CAN,GPIO EXP
- 07
- UART, RS232, RS485, EEPROM, SD
- 08
- POWER
- 09
- LVDS LCD
- 10
- MECHNICS
- 4.0V
sheet 4
- CARIER SODIMM INTERFACE
- NC - no external PHY on SB-iMX8X
- NC - no external PHY on SB-iMX8X
- STITCHING CAPACITORS
- PLANE STITCHING
- CAPACITORS
sheet 5
- ETHERNET 1
- ETHERNET 2
- 100 Ohm
- 100 Ohm
- 100 Ohm
- 100 Ohm
- 100 Ohm
- 100 Ohm
- 100 Ohm
- 100 Ohm
- Layout notes
  1: 100ohm differential impedance control.
  2: Match each differential signals pair ± 5 mils.
  3: Not more than two vias on each differential trace
  4: GND stitching VIA near every signal VIA
  5: The spacing between differential pair signals and other signals should be at least three times the trace width.
sheet 6
- USB OTG
- DNP
- >2.4
- USB 2.0 DUAL CONN
- 90 ohm
- 90 ohm
- mini PCIe & SIM
- DNP
- DNP
- Validate if those resistors
  required after bring up
sheet 7
- POWER/RESET/BOOT SWITCHES & JTAG
- Quad SPI boot
- JTAG HEADER
- QSPI BOOT jumper
- DNP
- TMS
- JTAG_VTREF
- TCK
- GND
- TDI
- TDO
- GND
- nRST
- DNP
- Added manualy.
- Does not appear
- in layout
- 100mil CONN 1
- 100mil CONN 2
- Signals can be swaped freely
- Signals can be swaped freely
  except jumper dependent like
  alt_boot
- alt_boot jumper
- alt boot - connect P21-7 with P21-8
- SILK
- DNP
- DNP
- EPPROM protect jumper
- WP - connect P21-31 with P21-32
- DNP
- Layout notes for PCIe and LVDS signals
  1: 100ohm differential impedance control for LVDS, 85ohm for PCIe.
  2: Match each differential signals pair ± 5 mils.
  3: Not more than two vias on each differential trace
  4: GND stitching VIA near every signal VIA
  5: The spacing between differential pair signal and other signals should at least three times the trace width.
sheet 8
- MIPI-CSI MODULE
  Based on SB-uCM design
- COMPATIBLE CAMERA MODULE: LI-OV5640-MIPI-AF
- Default I2C address (SCCB slave ID): 0x78
- DNP
- DNP
- DNP
- DNP
- DNP
- DNP
- DNP
- MCLK PROVISIONS
- DNP
- up to 140mA
- DNP
- DNP
- DNP
- CSI HEADER
- DNP
- DNP
- CAN
- VSB_1V5, VSB_1V8 & VCC_2V8 CSI sources
- CAN0 TRANSCEIVER
- SILK
- CAN0 VCC jumper
- Vout=Vfb*(1+Rt/Rb)=0.8*(1+13.3/10)=1.86V
- DNP
- SILK
- CAN0 GND jumper
- DNP
- Vout=Vfb*(1+Rt/Rb)=0.8*(1+16.5/6.49)=2.8V
- CAN2 TRANSCEIVER
- SILK
- CAN2 VCC jumper
- Vout=Vfb*(1+Rt/Rb)=0.8*(1+9.1/10)=1.528V
- SILK
- CAN2 GND jumper
- GPIO EXPANDER
- SILK
- Force PCIe to mPCIe
- Layout notes
  1: 100ohm differential impedance control for CSI, 85 for PCIe, 90 for USB.
  2: Match each differential signals pair ± 5 mils and 40 mils for usb
  3: Not more than two vias on each differential trace
  4: GND stitching VIA near every signal VIA
  5: The spacing between differential pair signal and other signals should at least three times the trace width.
- I2C address: 0x20
